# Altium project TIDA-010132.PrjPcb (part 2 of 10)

## Sheet AFE1.SchDoc
size 558 x 431 mm; Date: Not shown in title block; ApprovedBy: Not shown in title block; CheckedBy: Not shown in title block; Author: Not shown in title block; CompanyName: Not shown in title block; DrawnBy: Avinash N; Engineer: Not shown in title block; Organization: Not shown in title block; Address1: Not shown in title block; Address2: Not shown in title block; Address3: Not shown in title block; Address4: Not shown in title block; DocumentNumber: 1; Revision: Use project parameter SCH_Rev; SheetNumber: 4; SheetTotal: 32; PageSetup: Record=PageOptions¦CenterHorizontal=True¦CenterVertical=True¦PrintScale=1.00¦XCorrection=1.00¦YCorrection=1.00¦PrintKind=0¦BorderSize=5000000¦LeftOffset=0¦BottomOffset=0¦Orientation=2¦PaperLength=1000¦PaperWidth=1000¦Scale=100¦PaperSource=15¦PrintQuality=600¦MediaType=1¦DitherType=10¦PaperKind=Letter¦PrintScaleMode=1
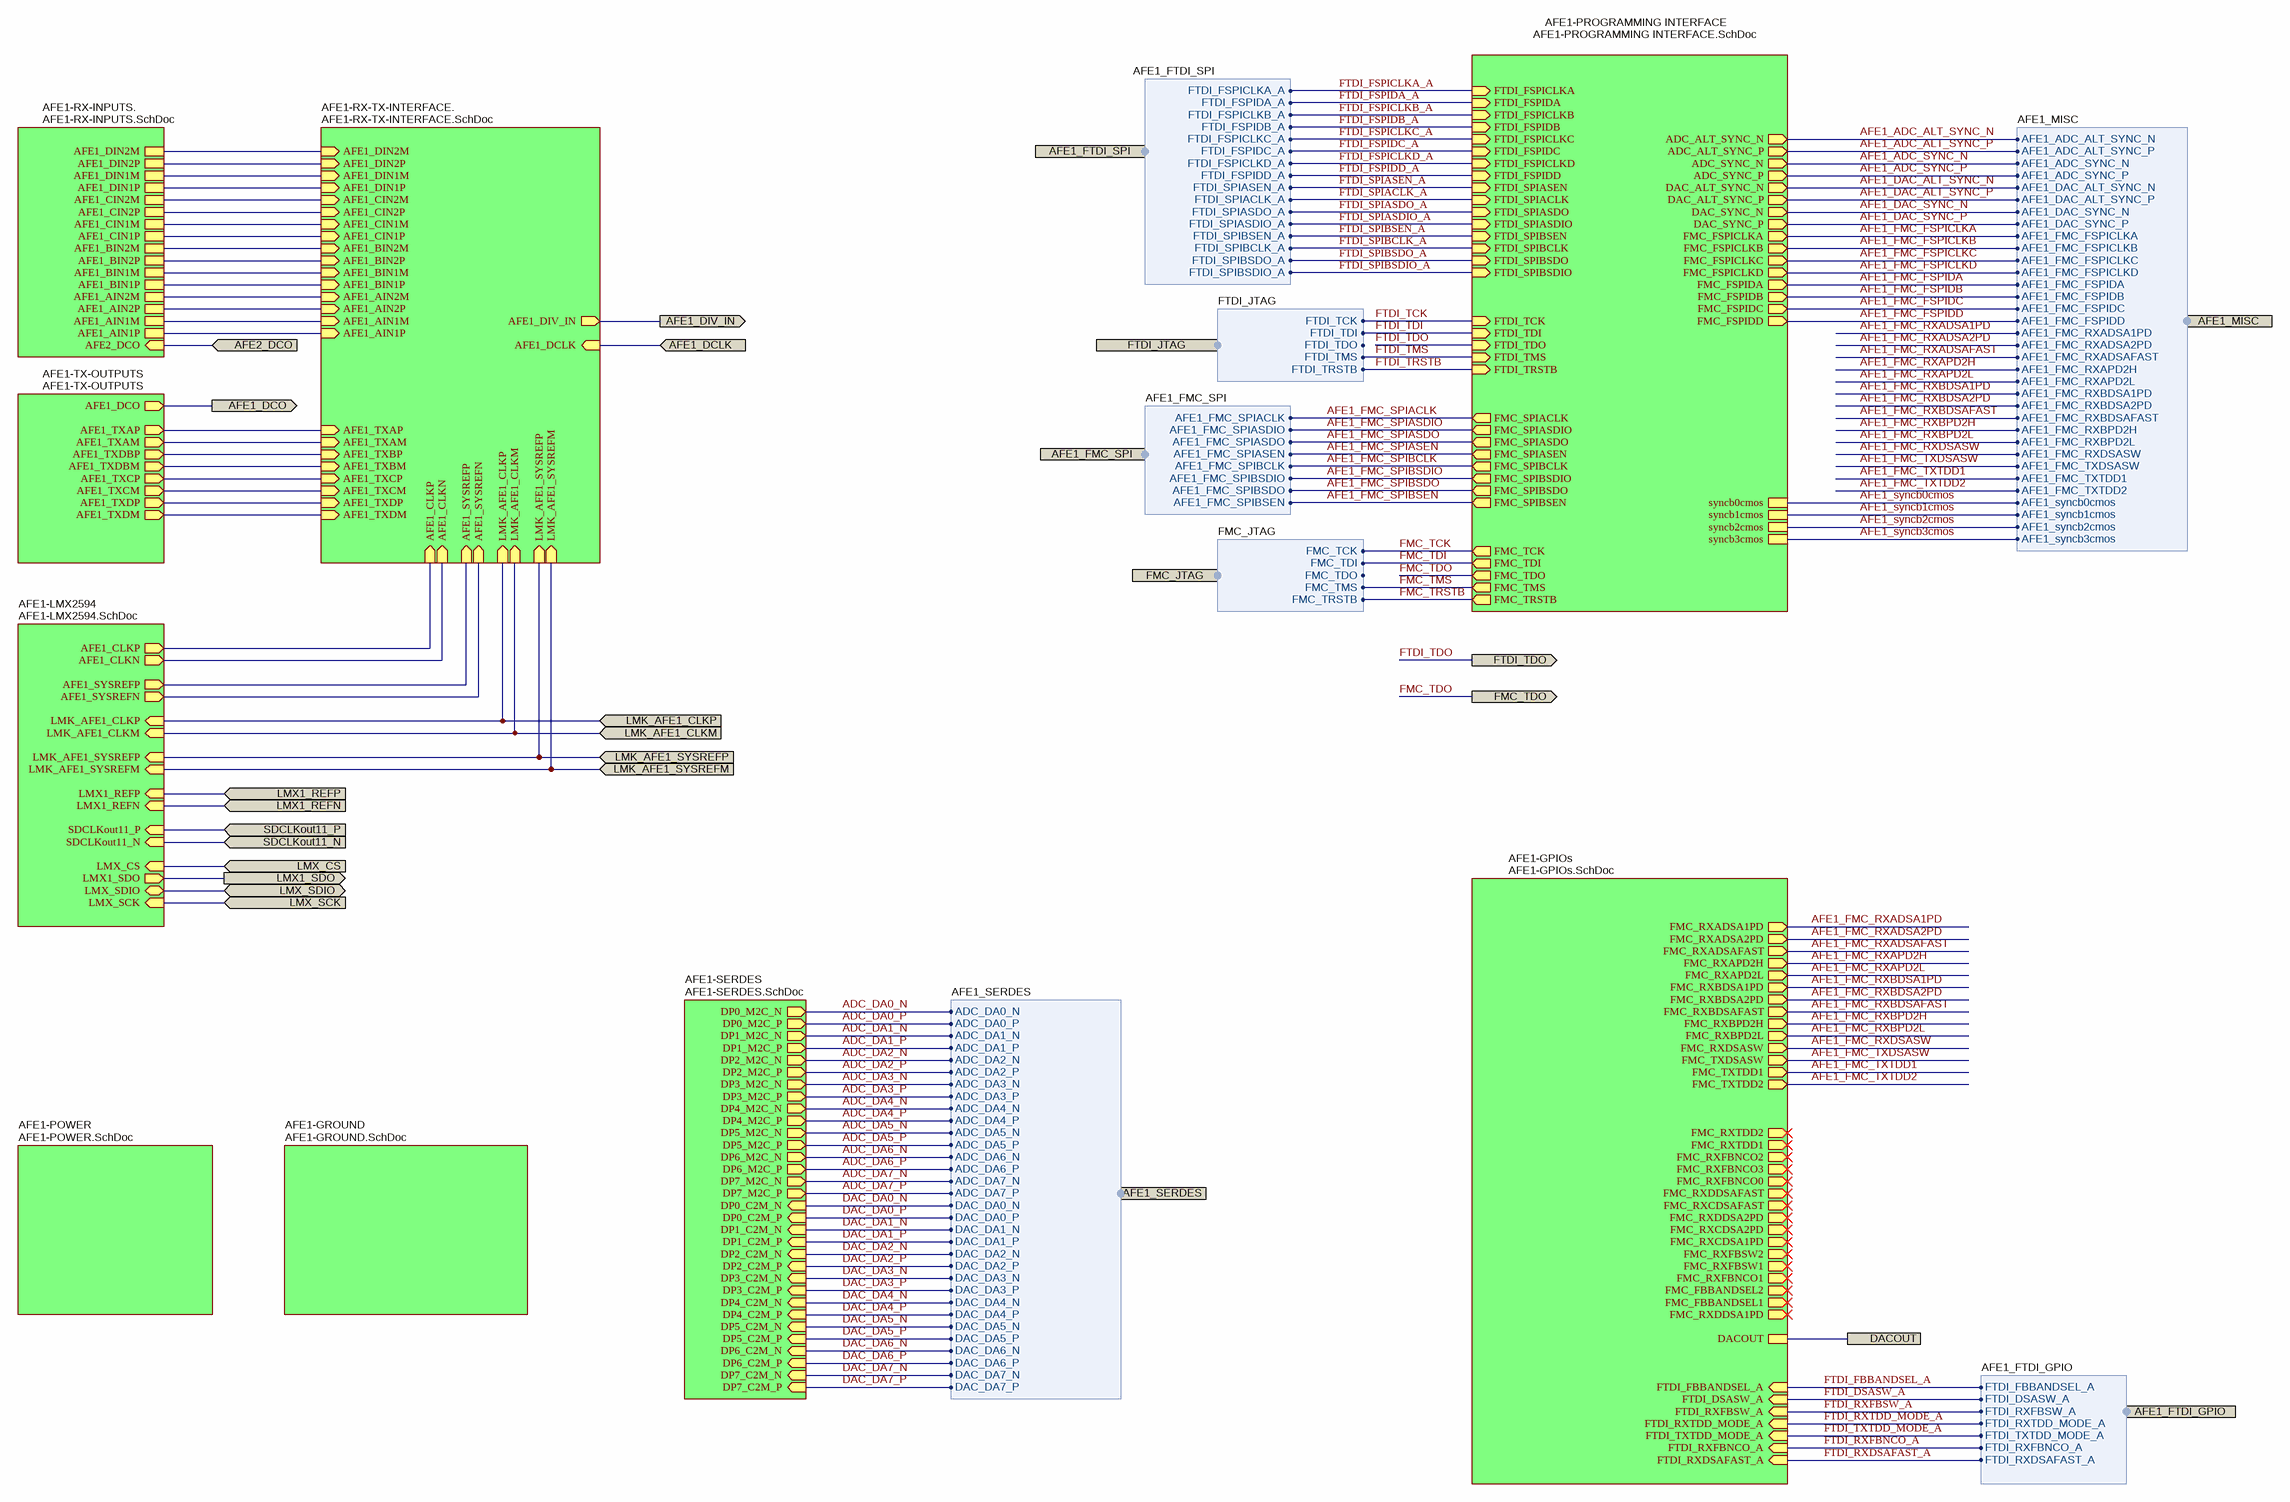
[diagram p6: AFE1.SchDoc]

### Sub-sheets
AFE1-GPIOs = AFE1-GPIOs.SchDoc: FMC_RXADSA1PD (out), FMC_RXADSA2PD (out), FMC_RXADSAFAST (out), FMC_RXAPD2H (out), FMC_RXAPD2L (out), FMC_RXBDSA1PD (out), FMC_RXBDSA2PD (out), FMC_RXBDSAFAST (out), FMC_RXBPD2H (out), FMC_RXBPD2L (out), FMC_RXDSASW (out), FMC_TXDSASW (out), FMC_TXTDD1 (out), FMC_TXTDD2 (out), FMC_RXTDD2 (out), FMC_RXTDD1 (out), FMC_RXFBNCO2 (out), FMC_RXFBNCO3 (out), FMC_RXFBNCO0 (out), FMC_RXDDSAFAST (out), FMC_RXCDSAFAST (out), FMC_RXDDSA2PD (out), FMC_RXCDSA2PD (out), FMC_RXCDSA1PD (out), FMC_RXFBSW2 (out), FMC_RXFBSW1 (out), FMC_RXFBNCO1 (out), FMC_FBBANDSEL2 (out), FMC_FBBANDSEL1 (out), DACOUT, FTDI_RXFBNCO_A (in), FTDI_RXDSAFAST_A (in), FTDI_DSASW_A (in), FTDI_RXFBSW_A (in), FTDI_RXTDD_MODE_A (in), FTDI_TXTDD_MODE_A (in), FTDI_FBBANDSEL_A (in), FMC_RXDDSA1PD (out)
AFE1-GROUND = AFE1-GROUND.SchDoc: no entries
AFE1-LMX2594 = AFE1-LMX2594.SchDoc: AFE1_CLKP (out), AFE1_CLKN (out), AFE1_SYSREFP (out), AFE1_SYSREFN (out), SDCLKout11_P (in), SDCLKout11_N (in), LMK_AFE1_CLKP (in), LMK_AFE1_CLKM (in), LMX_CS (in), LMX_SDIO (bidir), LMX_SCK (in), LMX1_SDO (out), LMK_AFE1_SYSREFP (in), LMK_AFE1_SYSREFM (in), LMX1_REFP (in), LMX1_REFN (in)
AFE1-POWER = AFE1-POWER.SchDoc: no entries
AFE1-PROGRAMMING INTERFACE = AFE1-PROGRAMMING INTERFACE.SchDoc: ADC_ALT_SYNC_P (out), ADC_ALT_SYNC_N (out), ADC_SYNC_P (out), ADC_SYNC_N (out), DAC_ALT_SYNC_P (out), DAC_ALT_SYNC_N (out), DAC_SYNC_P (out), DAC_SYNC_N (out), FMC_FSPICLKA (out), FMC_FSPICLKB (out), FMC_FSPICLKC (out), FMC_FSPICLKD (out), FMC_FSPIDA (out), FMC_FSPIDB (out), FMC_FSPIDC (out), FMC_FSPIDD (out), syncb0cmos, syncb1cmos, syncb2cmos, syncb3cmos, FMC_TMS (out), FMC_TCK (out), FMC_TDO (out), FMC_TDI (out), FMC_TRSTB (out), FMC_SPIASEN (out), FMC_SPIACLK (out), FMC_SPIASDO (out), FMC_SPIASDIO (out), FMC_SPIBSEN (out), FMC_SPIBCLK (out), FMC_SPIBSDO (out), FMC_SPIBSDIO (out), FTDI_TDI (in), FTDI_TDO (in), FTDI_TMS (in), FTDI_TRSTB (in), FTDI_TCK (in), FTDI_FSPIDD (in), FTDI_SPIASEN (in), FTDI_SPIBCLK (in), FTDI_SPIASDIO (in), FTDI_SPIBSEN (in), FTDI_SPIBSDO (in), FTDI_SPIBSDIO (in), FTDI_FSPIDC (in), FTDI_FSPICLKC (in), FTDI_FSPIDB (in), FTDI_FSPICLKB (in), FTDI_FSPIDA (in), FTDI_FSPICLKA (in), FTDI_FSPICLKD (in), FTDI_SPIASDO (in), FTDI_SPIACLK (in)
AFE1-RX-INPUTS. = AFE1-RX-INPUTS.SchDoc: AFE1_CIN1M, AFE1_BIN2P, AFE1_AIN2P, AFE1_DIN2P, AFE1_BIN2M, AFE1_CIN1P, AFE1_DIN2M, AFE1_AIN1M, AFE1_DIN1P, AFE1_BIN1M, AFE1_AIN2M, AFE1_DIN1M, AFE1_CIN2P, AFE1_CIN2M, AFE1_AIN1P, AFE1_BIN1P, AFE2_DCO (in)
AFE1-RX-TX-INTERFACE. = AFE1-RX-TX-INTERFACE.SchDoc: AFE1_DIN1M (in), AFE1_CIN1M (in), AFE1_BIN1M (in), AFE1_CIN2M (in), AFE1_AIN2M (in), AFE1_DIN2M (in), AFE1_DIN1P (in), AFE1_BIN2P (in), AFE1_CIN1P (in), AFE1_CLKN (in), AFE1_CLKP (in), AFE1_DIV_IN (out), AFE1_SYSREFN (in), AFE1_SYSREFP (in), AFE1_AIN1P (in), AFE1_AIN1M (in), AFE1_DIN2P (in), AFE1_CIN2P (in), AFE1_BIN2M (in), AFE1_BIN1P (in), AFE1_AIN2P (in), LMK_AFE1_CLKP (in), LMK_AFE1_CLKM (in), AFE1_TXAP (in), AFE1_TXAM (in), AFE1_TXBM (in), AFE1_TXBP (in), AFE1_TXCM (in), AFE1_TXCP (in), AFE1_TXDM (in), AFE1_TXDP (in), AFE1_DCLK (in), LMK_AFE1_SYSREFM (in), LMK_AFE1_SYSREFP (in)
AFE1-SERDES = AFE1-SERDES.SchDoc: DP1_M2C_N (out), DP1_M2C_P (out), DP5_C2M_P (in), DP3_M2C_P (out), DP7_M2C_P (out), DP3_M2C_N (out), DP7_M2C_N (out), DP6_M2C_P (out), DP7_C2M_P (in), DP2_M2C_P (out), DP6_C2M_P (in), DP2_M2C_N (out), DP0_M2C_P (out), DP0_M2C_N (out), DP4_C2M_N (in), DP2_C2M_N (in), DP0_C2M_P (in), DP5_M2C_P (out), DP6_C2M_N (in), DP6_M2C_N (out), DP4_C2M_P (in), DP3_C2M_N (in), DP4_M2C_P (out), DP1_C2M_N (in), DP3_C2M_P (in), DP5_M2C_N (out), DP0_C2M_N (in), DP4_M2C_N (out), DP2_C2M_P (in), DP7_C2M_N (in), DP1_C2M_P (in), DP5_C2M_N (in)
AFE1-TX-OUTPUTS = AFE1-TX-OUTPUTS: AFE1_TXAM (out), AFE1_TXAP (out), AFE1_TXDBM (out), AFE1_TXDBP (out), AFE1_TXCM (out), AFE1_TXCP (out), AFE1_TXDM (out), AFE1_TXDP (out), AFE1_DCO (out)

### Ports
AFE1_DCLK (in), AFE1_DCO (out), AFE1_DIV_IN (out), AFE1_FMC_SPI (harness AFE1_FMC_SPI), AFE1_FTDI_GPIO (harness AFE1_FTDI_GPIO), AFE1_FTDI_SPI (harness AFE1_FTDI_SPI), AFE1_MISC (harness AFE1_MISC), AFE1_SERDES (harness AFE1_SERDES), AFE2_DCO (in), DACOUT, FMC_JTAG (harness FMC_JTAG), FMC_TDO (out), FTDI_JTAG (harness FTDI_JTAG), FTDI_TDO (out), LMK_AFE1_CLKM (in), LMK_AFE1_CLKP (in), LMK_AFE1_SYSREFM (in), LMK_AFE1_SYSREFP (in), LMX1_REFN (in), LMX1_REFP (in), LMX1_SDO (out), LMX_CS (in), LMX_SCK (in), LMX_SDIO (bidir), SDCLKout11_N (in), SDCLKout11_P (in)

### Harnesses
AFE1_SERDES: ADC_DA0_N, ADC_DA0_P, ADC_DA1_N, ADC_DA1_P, ADC_DA2_N, ADC_DA2_P, ADC_DA3_N, ADC_DA3_P, ADC_DA4_N, ADC_DA4_P, ADC_DA5_N, ADC_DA5_P, ADC_DA6_N, ADC_DA6_P, ADC_DA7_N, ADC_DA7_P, DAC_DA0_N, DAC_DA0_P, DAC_DA1_N, DAC_DA1_P, DAC_DA2_N, DAC_DA2_P, DAC_DA3_N, DAC_DA3_P, DAC_DA4_N, DAC_DA4_P, DAC_DA5_N, DAC_DA5_P, DAC_DA6_N, DAC_DA6_P, DAC_DA7_N, DAC_DA7_P
AFE1_MISC: AFE1_ADC_ALT_SYNC_N, AFE1_ADC_ALT_SYNC_P, AFE1_ADC_SYNC_N, AFE1_ADC_SYNC_P, AFE1_DAC_ALT_SYNC_N, AFE1_DAC_ALT_SYNC_P, AFE1_DAC_SYNC_N, AFE1_DAC_SYNC_P, AFE1_FMC_FSPICLKA, AFE1_FMC_FSPICLKB, AFE1_FMC_FSPICLKC, AFE1_FMC_FSPICLKD, AFE1_FMC_FSPIDA, AFE1_FMC_FSPIDB, AFE1_FMC_FSPIDC, AFE1_FMC_FSPIDD, AFE1_FMC_RXADSA1PD, AFE1_FMC_RXADSA2PD, AFE1_FMC_RXADSAFAST, AFE1_FMC_RXAPD2H, AFE1_FMC_RXAPD2L, AFE1_FMC_RXBDSA1PD, AFE1_FMC_RXBDSA2PD, AFE1_FMC_RXBDSAFAST, AFE1_FMC_RXBPD2H, AFE1_FMC_RXBPD2L, AFE1_FMC_RXDSASW, AFE1_FMC_TXDSASW, AFE1_FMC_TXTDD1, AFE1_FMC_TXTDD2, AFE1_syncb0cmos, AFE1_syncb1cmos, AFE1_syncb2cmos, AFE1_syncb3cmos
FMC_JTAG: FMC_TCK, FMC_TDI, FMC_TDO, FMC_TMS, FMC_TRSTB
AFE1_FTDI_GPIO: FTDI_FBBANDSEL_A, FTDI_DSASW_A, FTDI_RXFBSW_A, FTDI_RXTDD_MODE_A, FTDI_TXTDD_MODE_A, FTDI_RXFBNCO_A, FTDI_RXDSAFAST_A
FTDI_JTAG: FTDI_TCK, FTDI_TDI, FTDI_TDO, FTDI_TMS, FTDI_TRSTB
AFE1_FTDI_SPI: FTDI_FSPICLKA_A, FTDI_FSPIDA_A, FTDI_FSPICLKB_A, FTDI_FSPIDB_A, FTDI_FSPICLKC_A, FTDI_FSPIDC_A, FTDI_FSPICLKD_A, FTDI_FSPIDD_A, FTDI_SPIASEN_A, FTDI_SPIACLK_A, FTDI_SPIASDO_A, FTDI_SPIASDIO_A, FTDI_SPIBSEN_A, FTDI_SPIBCLK_A, FTDI_SPIBSDO_A, FTDI_SPIBSDIO_A
AFE1_FMC_SPI: AFE1_FMC_SPIACLK, AFE1_FMC_SPIASDIO, AFE1_FMC_SPIASDO, AFE1_FMC_SPIASEN, AFE1_FMC_SPIBCLK, AFE1_FMC_SPIBSDIO, AFE1_FMC_SPIBSDO, AFE1_FMC_SPIBSEN

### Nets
ADC_DA0_N: sheet AFE1-SERDES/DP0_M2C_N, port AFE1_SERDES.ADC_DA0_N
ADC_DA0_P: sheet AFE1-SERDES/DP0_M2C_P, port AFE1_SERDES.ADC_DA0_P
ADC_DA1_N: sheet AFE1-SERDES/DP1_M2C_N, port AFE1_SERDES.ADC_DA1_N
ADC_DA1_P: sheet AFE1-SERDES/DP1_M2C_P, port AFE1_SERDES.ADC_DA1_P
ADC_DA2_N: sheet AFE1-SERDES/DP2_M2C_N, port AFE1_SERDES.ADC_DA2_N
ADC_DA2_P: sheet AFE1-SERDES/DP2_M2C_P, port AFE1_SERDES.ADC_DA2_P
ADC_DA3_N: sheet AFE1-SERDES/DP3_M2C_N, port AFE1_SERDES.ADC_DA3_N
ADC_DA3_P: sheet AFE1-SERDES/DP3_M2C_P, port AFE1_SERDES.ADC_DA3_P
ADC_DA4_N: sheet AFE1-SERDES/DP4_M2C_N, port AFE1_SERDES.ADC_DA4_N
ADC_DA4_P: sheet AFE1-SERDES/DP4_M2C_P, port AFE1_SERDES.ADC_DA4_P
ADC_DA5_N: sheet AFE1-SERDES/DP5_M2C_N, port AFE1_SERDES.ADC_DA5_N
ADC_DA5_P: sheet AFE1-SERDES/DP5_M2C_P, port AFE1_SERDES.ADC_DA5_P
ADC_DA6_N: sheet AFE1-SERDES/DP6_M2C_N, port AFE1_SERDES.ADC_DA6_N
ADC_DA6_P: sheet AFE1-SERDES/DP6_M2C_P, port AFE1_SERDES.ADC_DA6_P
ADC_DA7_N: sheet AFE1-SERDES/DP7_M2C_N, port AFE1_SERDES.ADC_DA7_N
ADC_DA7_P: sheet AFE1-SERDES/DP7_M2C_P, port AFE1_SERDES.ADC_DA7_P
AFE1_ADC_ALT_SYNC_N: sheet AFE1-PROGRAMMING INTERFACE/ADC_ALT_SYNC_N, port AFE1_MISC.AFE1_ADC_ALT_SYNC_N
AFE1_ADC_ALT_SYNC_P: sheet AFE1-PROGRAMMING INTERFACE/ADC_ALT_SYNC_P, port AFE1_MISC.AFE1_ADC_ALT_SYNC_P
AFE1_ADC_SYNC_N: sheet AFE1-PROGRAMMING INTERFACE/ADC_SYNC_N, port AFE1_MISC.AFE1_ADC_SYNC_N
AFE1_ADC_SYNC_P: sheet AFE1-PROGRAMMING INTERFACE/ADC_SYNC_P, port AFE1_MISC.AFE1_ADC_SYNC_P
AFE1_DAC_ALT_SYNC_N: sheet AFE1-PROGRAMMING INTERFACE/DAC_ALT_SYNC_N, port AFE1_MISC.AFE1_DAC_ALT_SYNC_N
AFE1_DAC_ALT_SYNC_P: sheet AFE1-PROGRAMMING INTERFACE/DAC_ALT_SYNC_P, port AFE1_MISC.AFE1_DAC_ALT_SYNC_P
AFE1_DAC_SYNC_N: sheet AFE1-PROGRAMMING INTERFACE/DAC_SYNC_N, port AFE1_MISC.AFE1_DAC_SYNC_N
AFE1_DAC_SYNC_P: sheet AFE1-PROGRAMMING INTERFACE/DAC_SYNC_P, port AFE1_MISC.AFE1_DAC_SYNC_P
AFE1_DCLK: port AFE1_DCLK, sheet AFE1-RX-TX-INTERFACE./AFE1_DCLK
AFE1_DCO: port AFE1_DCO, sheet AFE1-TX-OUTPUTS/AFE1_DCO
AFE1_DIV_IN: port AFE1_DIV_IN, sheet AFE1-RX-TX-INTERFACE./AFE1_DIV_IN
AFE1_FMC_FSPICLKA: sheet AFE1-PROGRAMMING INTERFACE/FMC_FSPICLKA, port AFE1_MISC.AFE1_FMC_FSPICLKA
AFE1_FMC_FSPICLKB: sheet AFE1-PROGRAMMING INTERFACE/FMC_FSPICLKB, port AFE1_MISC.AFE1_FMC_FSPICLKB
AFE1_FMC_FSPICLKC: sheet AFE1-PROGRAMMING INTERFACE/FMC_FSPICLKC, port AFE1_MISC.AFE1_FMC_FSPICLKC
AFE1_FMC_FSPICLKD: sheet AFE1-PROGRAMMING INTERFACE/FMC_FSPICLKD, port AFE1_MISC.AFE1_FMC_FSPICLKD
AFE1_FMC_FSPIDA: sheet AFE1-PROGRAMMING INTERFACE/FMC_FSPIDA, port AFE1_MISC.AFE1_FMC_FSPIDA
AFE1_FMC_FSPIDB: sheet AFE1-PROGRAMMING INTERFACE/FMC_FSPIDB, port AFE1_MISC.AFE1_FMC_FSPIDB
AFE1_FMC_FSPIDC: sheet AFE1-PROGRAMMING INTERFACE/FMC_FSPIDC, port AFE1_MISC.AFE1_FMC_FSPIDC
AFE1_FMC_FSPIDD: sheet AFE1-PROGRAMMING INTERFACE/FMC_FSPIDD, port AFE1_MISC.AFE1_FMC_FSPIDD
AFE1_FMC_RXADSA1PD: sheet AFE1-GPIOs/FMC_RXADSA1PD, port AFE1_MISC.AFE1_FMC_RXADSA1PD
AFE1_FMC_RXADSA2PD: sheet AFE1-GPIOs/FMC_RXADSA2PD, port AFE1_MISC.AFE1_FMC_RXADSA2PD
AFE1_FMC_RXADSAFAST: sheet AFE1-GPIOs/FMC_RXADSAFAST, port AFE1_MISC.AFE1_FMC_RXADSAFAST
AFE1_FMC_RXAPD2H: sheet AFE1-GPIOs/FMC_RXAPD2H, port AFE1_MISC.AFE1_FMC_RXAPD2H
AFE1_FMC_RXAPD2L: sheet AFE1-GPIOs/FMC_RXAPD2L, port AFE1_MISC.AFE1_FMC_RXAPD2L
AFE1_FMC_RXBDSA1PD: sheet AFE1-GPIOs/FMC_RXBDSA1PD, port AFE1_MISC.AFE1_FMC_RXBDSA1PD
AFE1_FMC_RXBDSA2PD: sheet AFE1-GPIOs/FMC_RXBDSA2PD, port AFE1_MISC.AFE1_FMC_RXBDSA2PD
AFE1_FMC_RXBDSAFAST: sheet AFE1-GPIOs/FMC_RXBDSAFAST, port AFE1_MISC.AFE1_FMC_RXBDSAFAST
AFE1_FMC_RXBPD2H: sheet AFE1-GPIOs/FMC_RXBPD2H, port AFE1_MISC.AFE1_FMC_RXBPD2H
AFE1_FMC_RXBPD2L: sheet AFE1-GPIOs/FMC_RXBPD2L, port AFE1_MISC.AFE1_FMC_RXBPD2L
AFE1_FMC_RXDSASW: sheet AFE1-GPIOs/FMC_RXDSASW, port AFE1_MISC.AFE1_FMC_RXDSASW
AFE1_FMC_SPIACLK: sheet AFE1-PROGRAMMING INTERFACE/FMC_SPIACLK, port AFE1_FMC_SPI.AFE1_FMC_SPIACLK
AFE1_FMC_SPIASDIO: sheet AFE1-PROGRAMMING INTERFACE/FMC_SPIASDIO, port AFE1_FMC_SPI.AFE1_FMC_SPIASDIO
AFE1_FMC_SPIASDO: sheet AFE1-PROGRAMMING INTERFACE/FMC_SPIASDO, port AFE1_FMC_SPI.AFE1_FMC_SPIASDO
AFE1_FMC_SPIASEN: sheet AFE1-PROGRAMMING INTERFACE/FMC_SPIASEN, port AFE1_FMC_SPI.AFE1_FMC_SPIASEN
AFE1_FMC_SPIBCLK: sheet AFE1-PROGRAMMING INTERFACE/FMC_SPIBCLK, port AFE1_FMC_SPI.AFE1_FMC_SPIBCLK
AFE1_FMC_SPIBSDIO: sheet AFE1-PROGRAMMING INTERFACE/FMC_SPIBSDIO, port AFE1_FMC_SPI.AFE1_FMC_SPIBSDIO
AFE1_FMC_SPIBSDO: sheet AFE1-PROGRAMMING INTERFACE/FMC_SPIBSDO, port AFE1_FMC_SPI.AFE1_FMC_SPIBSDO
AFE1_FMC_SPIBSEN: sheet AFE1-PROGRAMMING INTERFACE/FMC_SPIBSEN, port AFE1_FMC_SPI.AFE1_FMC_SPIBSEN
AFE1_FMC_TXDSASW: sheet AFE1-GPIOs/FMC_TXDSASW, port AFE1_MISC.AFE1_FMC_TXDSASW
AFE1_FMC_TXTDD1: sheet AFE1-GPIOs/FMC_TXTDD1, port AFE1_MISC.AFE1_FMC_TXTDD1
AFE1_FMC_TXTDD2: sheet AFE1-GPIOs/FMC_TXTDD2, port AFE1_MISC.AFE1_FMC_TXTDD2
AFE1_syncb0cmos: sheet AFE1-PROGRAMMING INTERFACE/syncb0cmos, port AFE1_MISC.AFE1_syncb0cmos
AFE1_syncb1cmos: sheet AFE1-PROGRAMMING INTERFACE/syncb1cmos, port AFE1_MISC.AFE1_syncb1cmos
AFE1_syncb2cmos: sheet AFE1-PROGRAMMING INTERFACE/syncb2cmos, port AFE1_MISC.AFE1_syncb2cmos
AFE1_syncb3cmos: sheet AFE1-PROGRAMMING INTERFACE/syncb3cmos, port AFE1_MISC.AFE1_syncb3cmos
AFE2_DCO: port AFE2_DCO, sheet AFE1-RX-INPUTS./AFE2_DCO
DAC_DA0_N: sheet AFE1-SERDES/DP0_C2M_N, port AFE1_SERDES.DAC_DA0_N
DAC_DA0_P: sheet AFE1-SERDES/DP0_C2M_P, port AFE1_SERDES.DAC_DA0_P
DAC_DA1_N: sheet AFE1-SERDES/DP1_C2M_N, port AFE1_SERDES.DAC_DA1_N
DAC_DA1_P: sheet AFE1-SERDES/DP1_C2M_P, port AFE1_SERDES.DAC_DA1_P
DAC_DA2_N: sheet AFE1-SERDES/DP2_C2M_N, port AFE1_SERDES.DAC_DA2_N
DAC_DA2_P: sheet AFE1-SERDES/DP2_C2M_P, port AFE1_SERDES.DAC_DA2_P
DAC_DA3_N: sheet AFE1-SERDES/DP3_C2M_N, port AFE1_SERDES.DAC_DA3_N
DAC_DA3_P: sheet AFE1-SERDES/DP3_C2M_P, port AFE1_SERDES.DAC_DA3_P
DAC_DA4_N: sheet AFE1-SERDES/DP4_C2M_N, port AFE1_SERDES.DAC_DA4_N
DAC_DA4_P: sheet AFE1-SERDES/DP4_C2M_P, port AFE1_SERDES.DAC_DA4_P
DAC_DA5_N: sheet AFE1-SERDES/DP5_C2M_N, port AFE1_SERDES.DAC_DA5_N
DAC_DA5_P: sheet AFE1-SERDES/DP5_C2M_P, port AFE1_SERDES.DAC_DA5_P
DAC_DA6_N: sheet AFE1-SERDES/DP6_C2M_N, port AFE1_SERDES.DAC_DA6_N
DAC_DA6_P: sheet AFE1-SERDES/DP6_C2M_P, port AFE1_SERDES.DAC_DA6_P
DAC_DA7_N: sheet AFE1-SERDES/DP7_C2M_N, port AFE1_SERDES.DAC_DA7_N
DAC_DA7_P: sheet AFE1-SERDES/DP7_C2M_P, port AFE1_SERDES.DAC_DA7_P
DACOUT: port DACOUT, sheet AFE1-GPIOs/DACOUT
FMC_TCK: sheet AFE1-PROGRAMMING INTERFACE/FMC_TCK, port FMC_JTAG.FMC_TCK
FMC_TDI: sheet AFE1-PROGRAMMING INTERFACE/FMC_TDI, port FMC_JTAG.FMC_TDI
FMC_TDO: port FMC_TDO, sheet AFE1-PROGRAMMING INTERFACE/FMC_TDO
FMC_TMS: sheet AFE1-PROGRAMMING INTERFACE/FMC_TMS, port FMC_JTAG.FMC_TMS
FMC_TRSTB: sheet AFE1-PROGRAMMING INTERFACE/FMC_TRSTB, port FMC_JTAG.FMC_TRSTB
FTDI_DSASW_A: sheet AFE1-GPIOs/FTDI_DSASW_A, port AFE1_FTDI_GPIO.FTDI_DSASW_A
FTDI_FBBANDSEL_A: sheet AFE1-GPIOs/FTDI_FBBANDSEL_A, port AFE1_FTDI_GPIO.FTDI_FBBANDSEL_A
FTDI_FSPICLKA_A: sheet AFE1-PROGRAMMING INTERFACE/FTDI_FSPICLKA, port AFE1_FTDI_SPI.FTDI_FSPICLKA_A
FTDI_FSPICLKB_A: sheet AFE1-PROGRAMMING INTERFACE/FTDI_FSPICLKB, port AFE1_FTDI_SPI.FTDI_FSPICLKB_A
FTDI_FSPICLKC_A: sheet AFE1-PROGRAMMING INTERFACE/FTDI_FSPICLKC, port AFE1_FTDI_SPI.FTDI_FSPICLKC_A
FTDI_FSPICLKD_A: sheet AFE1-PROGRAMMING INTERFACE/FTDI_FSPICLKD, port AFE1_FTDI_SPI.FTDI_FSPICLKD_A
FTDI_FSPIDA_A: sheet AFE1-PROGRAMMING INTERFACE/FTDI_FSPIDA, port AFE1_FTDI_SPI.FTDI_FSPIDA_A
FTDI_FSPIDB_A: sheet AFE1-PROGRAMMING INTERFACE/FTDI_FSPIDB, port AFE1_FTDI_SPI.FTDI_FSPIDB_A
FTDI_FSPIDC_A: sheet AFE1-PROGRAMMING INTERFACE/FTDI_FSPIDC, port AFE1_FTDI_SPI.FTDI_FSPIDC_A
FTDI_FSPIDD_A: sheet AFE1-PROGRAMMING INTERFACE/FTDI_FSPIDD, port AFE1_FTDI_SPI.FTDI_FSPIDD_A
FTDI_RXDSAFAST_A: sheet AFE1-GPIOs/FTDI_RXDSAFAST_A, port AFE1_FTDI_GPIO.FTDI_RXDSAFAST_A
FTDI_RXFBNCO_A: sheet AFE1-GPIOs/FTDI_RXFBNCO_A, port AFE1_FTDI_GPIO.FTDI_RXFBNCO_A
FTDI_RXFBSW_A: sheet AFE1-GPIOs/FTDI_RXFBSW_A, port AFE1_FTDI_GPIO.FTDI_RXFBSW_A
FTDI_RXTDD_MODE_A: sheet AFE1-GPIOs/FTDI_RXTDD_MODE_A, port AFE1_FTDI_GPIO.FTDI_RXTDD_MODE_A
FTDI_SPIACLK_A: sheet AFE1-PROGRAMMING INTERFACE/FTDI_SPIACLK, port AFE1_FTDI_SPI.FTDI_SPIACLK_A
FTDI_SPIASDIO_A: sheet AFE1-PROGRAMMING INTERFACE/FTDI_SPIASDIO, port AFE1_FTDI_SPI.FTDI_SPIASDIO_A
FTDI_SPIASDO_A: sheet AFE1-PROGRAMMING INTERFACE/FTDI_SPIASDO, port AFE1_FTDI_SPI.FTDI_SPIASDO_A
FTDI_SPIASEN_A: sheet AFE1-PROGRAMMING INTERFACE/FTDI_SPIASEN, port AFE1_FTDI_SPI.FTDI_SPIASEN_A
FTDI_SPIBCLK_A: sheet AFE1-PROGRAMMING INTERFACE/FTDI_SPIBCLK, port AFE1_FTDI_SPI.FTDI_SPIBCLK_A
FTDI_SPIBSDIO_A: sheet AFE1-PROGRAMMING INTERFACE/FTDI_SPIBSDIO, port AFE1_FTDI_SPI.FTDI_SPIBSDIO_A
FTDI_SPIBSDO_A: sheet AFE1-PROGRAMMING INTERFACE/FTDI_SPIBSDO, port AFE1_FTDI_SPI.FTDI_SPIBSDO_A
FTDI_SPIBSEN_A: sheet AFE1-PROGRAMMING INTERFACE/FTDI_SPIBSEN, port AFE1_FTDI_SPI.FTDI_SPIBSEN_A
FTDI_TCK: sheet AFE1-PROGRAMMING INTERFACE/FTDI_TCK, port FTDI_JTAG.FTDI_TCK
FTDI_TDI: sheet AFE1-PROGRAMMING INTERFACE/FTDI_TDI, port FTDI_JTAG.FTDI_TDI
FTDI_TDO: port FTDI_TDO, sheet AFE1-PROGRAMMING INTERFACE/FTDI_TDO
FTDI_TMS: sheet AFE1-PROGRAMMING INTERFACE/FTDI_TMS, port FTDI_JTAG.FTDI_TMS
FTDI_TRSTB: sheet AFE1-PROGRAMMING INTERFACE/FTDI_TRSTB, port FTDI_JTAG.FTDI_TRSTB
FTDI_TXTDD_MODE_A: sheet AFE1-GPIOs/FTDI_TXTDD_MODE_A, port AFE1_FTDI_GPIO.FTDI_TXTDD_MODE_A
LMK_AFE1_CLKM: port LMK_AFE1_CLKM, sheet AFE1-LMX2594/LMK_AFE1_CLKM, sheet AFE1-RX-TX-INTERFACE./LMK_AFE1_CLKM
LMK_AFE1_CLKP: port LMK_AFE1_CLKP, sheet AFE1-LMX2594/LMK_AFE1_CLKP, sheet AFE1-RX-TX-INTERFACE./LMK_AFE1_CLKP
LMK_AFE1_SYSREFM: port LMK_AFE1_SYSREFM, sheet AFE1-LMX2594/LMK_AFE1_SYSREFM, sheet AFE1-RX-TX-INTERFACE./LMK_AFE1_SYSREFM
LMK_AFE1_SYSREFP: port LMK_AFE1_SYSREFP, sheet AFE1-LMX2594/LMK_AFE1_SYSREFP, sheet AFE1-RX-TX-INTERFACE./LMK_AFE1_SYSREFP
LMX1_REFN: port LMX1_REFN, sheet AFE1-LMX2594/LMX1_REFN
LMX1_REFP: port LMX1_REFP, sheet AFE1-LMX2594/LMX1_REFP
LMX1_SDO: port LMX1_SDO, sheet AFE1-LMX2594/LMX1_SDO
LMX_CS: port LMX_CS, sheet AFE1-LMX2594/LMX_CS
LMX_SCK: port LMX_SCK, sheet AFE1-LMX2594/LMX_SCK
LMX_SDIO: port LMX_SDIO, sheet AFE1-LMX2594/LMX_SDIO
SDCLKout11_N: port SDCLKout11_N, sheet AFE1-LMX2594/SDCLKout11_N
SDCLKout11_P: port SDCLKout11_P, sheet AFE1-LMX2594/SDCLKout11_P
(unnamed): sheet AFE1-RX-INPUTS./AFE1_CIN1M, sheet AFE1-RX-TX-INTERFACE./AFE1_CIN1M
(unnamed): sheet AFE1-RX-INPUTS./AFE1_BIN2P, sheet AFE1-RX-TX-INTERFACE./AFE1_BIN2P  [a separate net that carries the same name]
(unnamed): sheet AFE1-RX-INPUTS./AFE1_AIN2P, sheet AFE1-RX-TX-INTERFACE./AFE1_AIN2P  [a separate net that carries the same name]
(unnamed): sheet AFE1-RX-INPUTS./AFE1_DIN2P, sheet AFE1-RX-TX-INTERFACE./AFE1_DIN2P  [a separate net that carries the same name]
(unnamed): sheet AFE1-RX-INPUTS./AFE1_BIN2M, sheet AFE1-RX-TX-INTERFACE./AFE1_BIN2M  [a separate net that carries the same name]
(unnamed): sheet AFE1-RX-INPUTS./AFE1_CIN1P, sheet AFE1-RX-TX-INTERFACE./AFE1_CIN1P  [a separate net that carries the same name]
(unnamed): sheet AFE1-RX-INPUTS./AFE1_DIN2M, sheet AFE1-RX-TX-INTERFACE./AFE1_DIN2M  [a separate net that carries the same name]
(unnamed): sheet AFE1-RX-INPUTS./AFE1_AIN1M, sheet AFE1-RX-TX-INTERFACE./AFE1_AIN1M  [a separate net that carries the same name]
(unnamed): sheet AFE1-RX-INPUTS./AFE1_DIN1P, sheet AFE1-RX-TX-INTERFACE./AFE1_DIN1P  [a separate net that carries the same name]
(unnamed): sheet AFE1-RX-INPUTS./AFE1_BIN1M, sheet AFE1-RX-TX-INTERFACE./AFE1_BIN1M  [a separate net that carries the same name]
(unnamed): sheet AFE1-RX-INPUTS./AFE1_AIN2M, sheet AFE1-RX-TX-INTERFACE./AFE1_AIN2M  [a separate net that carries the same name]
(unnamed): sheet AFE1-RX-INPUTS./AFE1_DIN1M, sheet AFE1-RX-TX-INTERFACE./AFE1_DIN1M  [a separate net that carries the same name]
(unnamed): sheet AFE1-RX-INPUTS./AFE1_CIN2P, sheet AFE1-RX-TX-INTERFACE./AFE1_CIN2P  [a separate net that carries the same name]
(unnamed): sheet AFE1-RX-INPUTS./AFE1_CIN2M, sheet AFE1-RX-TX-INTERFACE./AFE1_CIN2M  [a separate net that carries the same name]
(unnamed): sheet AFE1-RX-INPUTS./AFE1_AIN1P, sheet AFE1-RX-TX-INTERFACE./AFE1_AIN1P  [a separate net that carries the same name]
(unnamed): sheet AFE1-RX-INPUTS./AFE1_BIN1P, sheet AFE1-RX-TX-INTERFACE./AFE1_BIN1P  [a separate net that carries the same name]
(unnamed): sheet AFE1-TX-OUTPUTS/AFE1_TXAM, sheet AFE1-RX-TX-INTERFACE./AFE1_TXAM  [a separate net that carries the same name]
(unnamed): sheet AFE1-TX-OUTPUTS/AFE1_TXAP, sheet AFE1-RX-TX-INTERFACE./AFE1_TXAP  [a separate net that carries the same name]
(unnamed): sheet AFE1-TX-OUTPUTS/AFE1_TXDBM, sheet AFE1-RX-TX-INTERFACE./AFE1_TXBM  [a separate net that carries the same name]
(unnamed): sheet AFE1-TX-OUTPUTS/AFE1_TXDBP, sheet AFE1-RX-TX-INTERFACE./AFE1_TXBP  [a separate net that carries the same name]
(unnamed): sheet AFE1-TX-OUTPUTS/AFE1_TXCM, sheet AFE1-RX-TX-INTERFACE./AFE1_TXCM  [a separate net that carries the same name]
(unnamed): sheet AFE1-TX-OUTPUTS/AFE1_TXCP, sheet AFE1-RX-TX-INTERFACE./AFE1_TXCP  [a separate net that carries the same name]
(unnamed): sheet AFE1-TX-OUTPUTS/AFE1_TXDM, sheet AFE1-RX-TX-INTERFACE./AFE1_TXDM  [a separate net that carries the same name]
(unnamed): sheet AFE1-TX-OUTPUTS/AFE1_TXDP, sheet AFE1-RX-TX-INTERFACE./AFE1_TXDP  [a separate net that carries the same name]
(unnamed): sheet AFE1-LMX2594/AFE1_CLKP, sheet AFE1-RX-TX-INTERFACE./AFE1_CLKP  [a separate net that carries the same name]
(unnamed): sheet AFE1-LMX2594/AFE1_CLKN, sheet AFE1-RX-TX-INTERFACE./AFE1_CLKN  [a separate net that carries the same name]
(unnamed): sheet AFE1-LMX2594/AFE1_SYSREFP, sheet AFE1-RX-TX-INTERFACE./AFE1_SYSREFP  [a separate net that carries the same name]
(unnamed): sheet AFE1-LMX2594/AFE1_SYSREFN, sheet AFE1-RX-TX-INTERFACE./AFE1_SYSREFN  [a separate net that carries the same name]

## Sheet AFE1-RX-INPUTS.SchDoc
size 431 x 279 mm; Date: Not shown in title block; ApprovedBy: Not shown in title block; CheckedBy: Not shown in title block; Author: Not shown in title block; CompanyName: Not shown in title block; DrawnBy: Avinash N; Engineer: Not shown in title block; Organization: Not shown in title block; Address1: Not shown in title block; Address2: Not shown in title block; Address3: Not shown in title block; Address4: Not shown in title block; DocumentNumber: 1; Revision: Use project parameter SCH_Rev; SheetNumber: 6; SheetTotal: 32; PageSetup: Record=PageOptions¦CenterHorizontal=True¦CenterVertical=True¦PrintScale=1.00¦XCorrection=1.00¦YCorrection=1.00¦PrintKind=0¦BorderSize=5000000¦LeftOffset=0¦BottomOffset=0¦Orientation=2¦PaperLength=1000¦PaperWidth=1000¦Scale=100¦PaperSource=15¦PrintQuality=600¦MediaType=1¦DitherType=10¦PaperKind=Letter¦PrintScaleMode=1
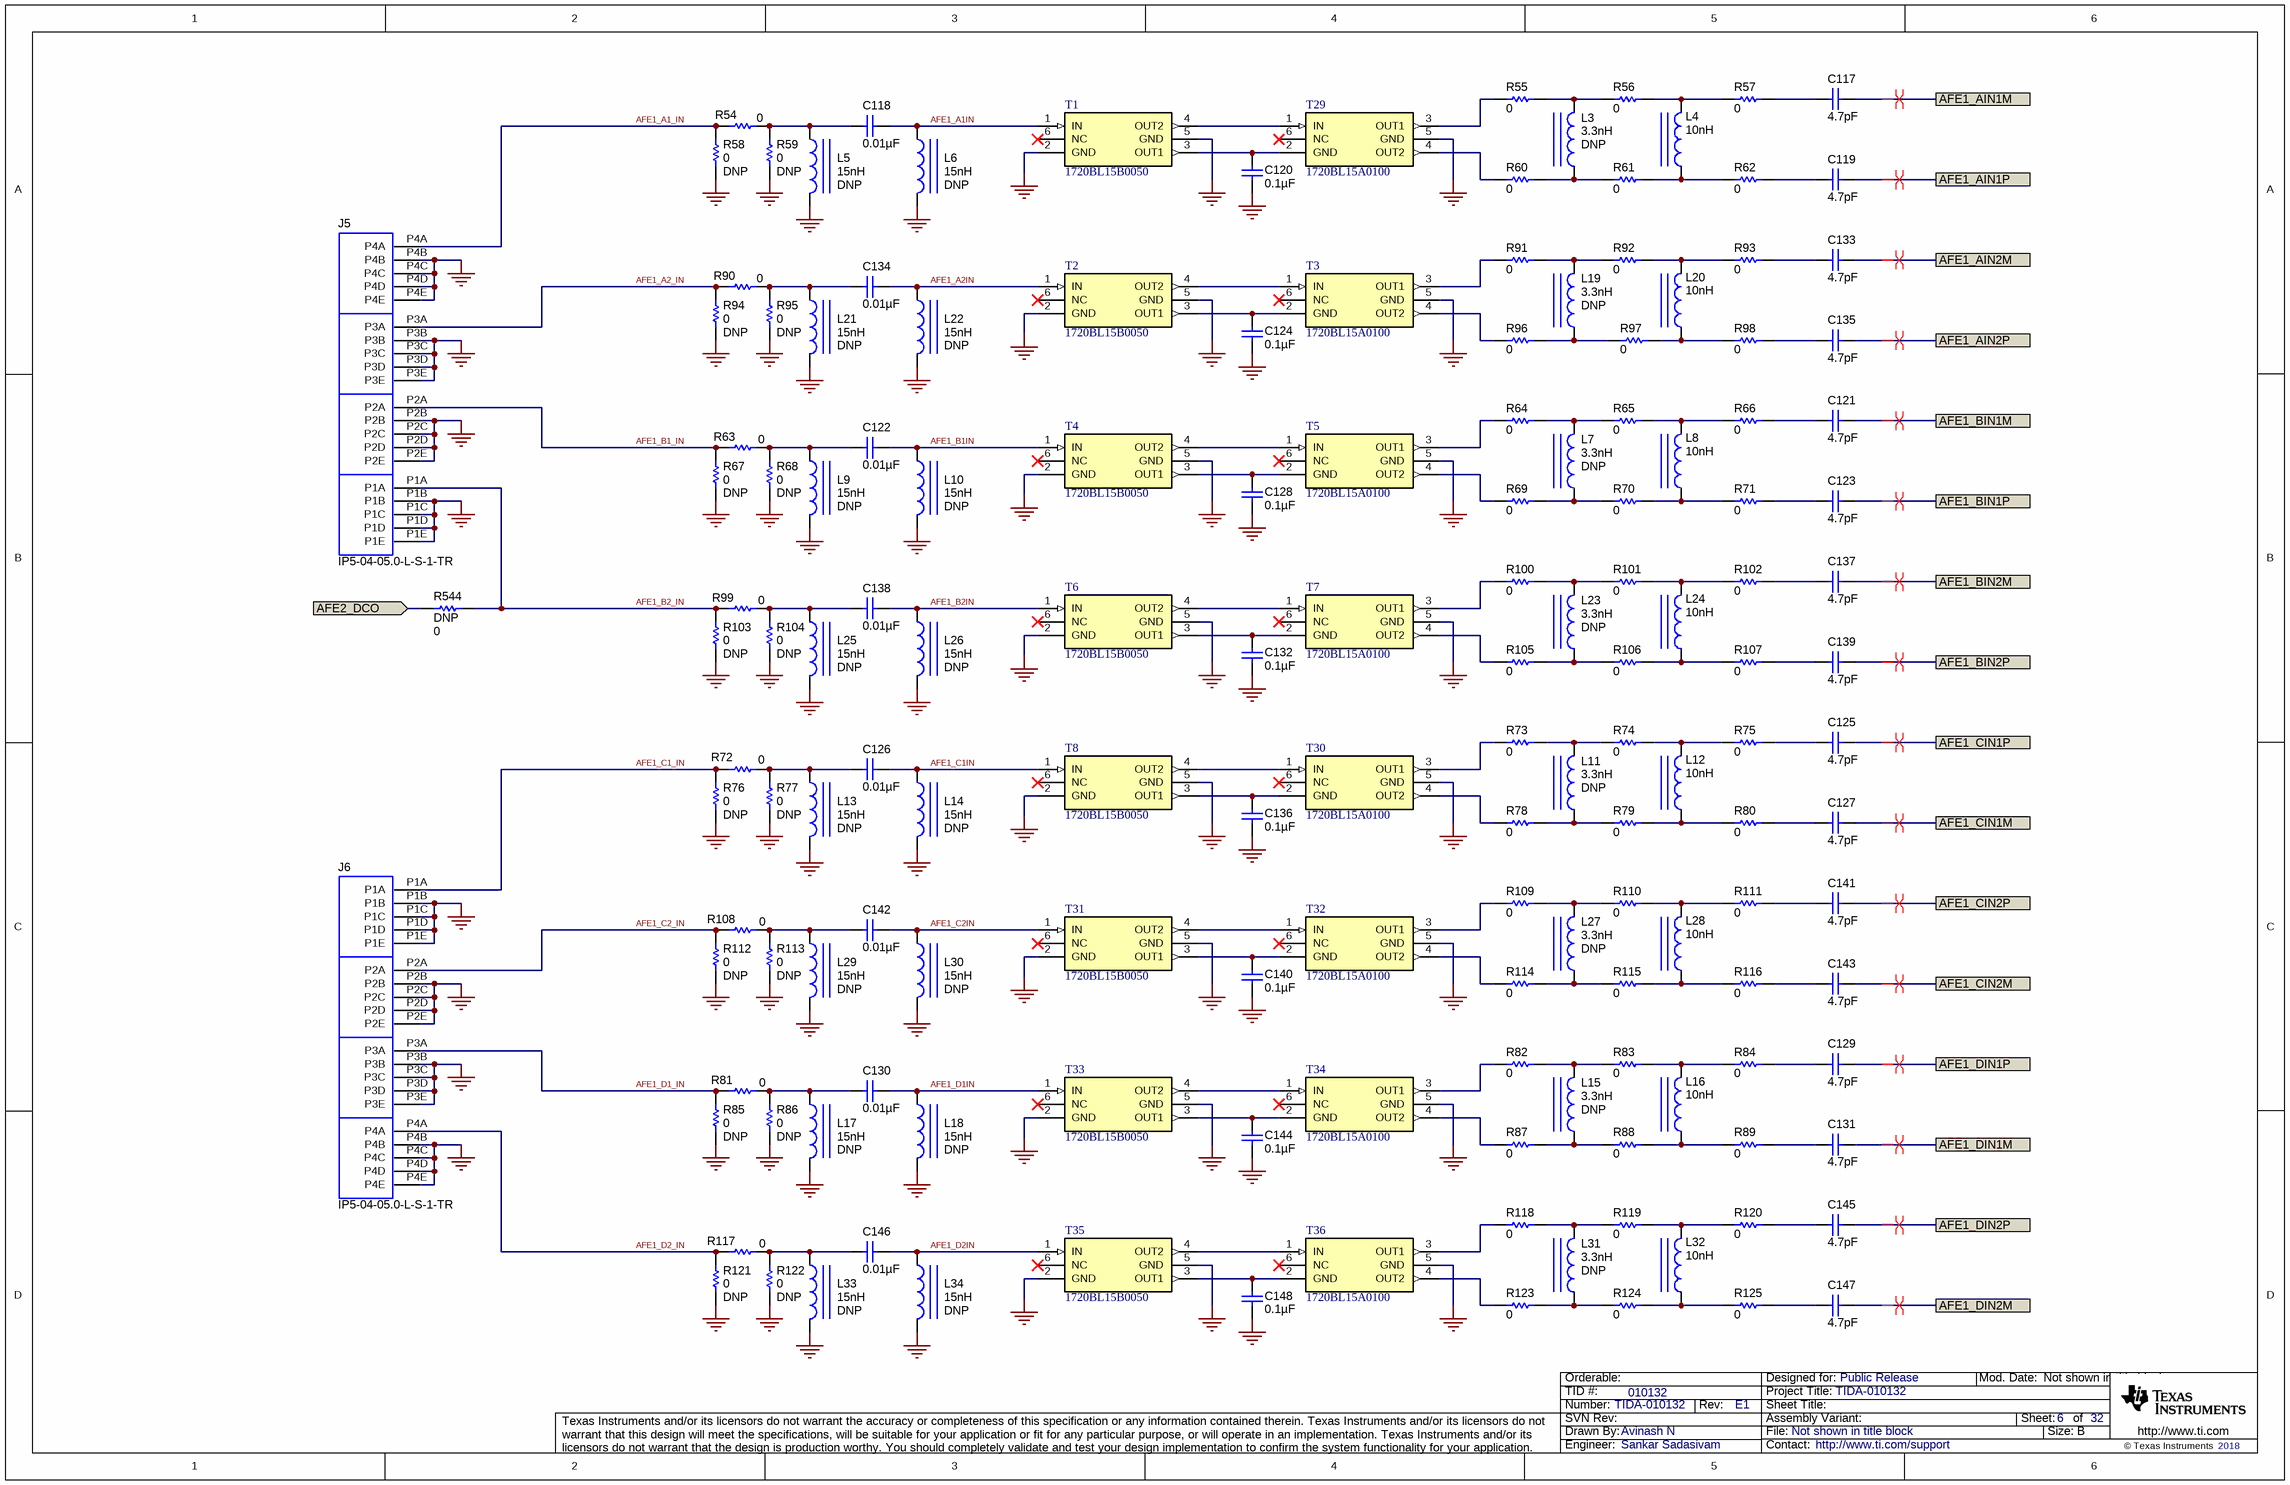
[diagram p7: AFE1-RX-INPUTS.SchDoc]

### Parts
C117  ValueDisplayed: 4.7pF  [0201]  (hidden comment: GRM0335C1H4R7CA01D)
C118  ValueDisplayed: 0.01µF  [0402]  (hidden comment: GRM155R71H103KA88D)
C119  ValueDisplayed: 4.7pF  [0201]  (hidden comment: GRM0335C1H4R7CA01D)
C120  ValueDisplayed: 0.1µF  [0201]  (hidden comment: GRM033C71A104KE14D)
C121  ValueDisplayed: 4.7pF  [0201]  (hidden comment: GRM0335C1H4R7CA01D)
C122  ValueDisplayed: 0.01µF  [0402]  (hidden comment: GRM155R71H103KA88D)
C123  ValueDisplayed: 4.7pF  [0201]  (hidden comment: GRM0335C1H4R7CA01D)
C124  ValueDisplayed: 0.1µF  [0201]  (hidden comment: GRM033C71A104KE14D)
C125  ValueDisplayed: 4.7pF  [0201]  (hidden comment: GRM0335C1H4R7CA01D)
C126  ValueDisplayed: 0.01µF  [0402]  (hidden comment: GRM155R71H103KA88D)
C127  ValueDisplayed: 4.7pF  [0201]  (hidden comment: GRM0335C1H4R7CA01D)
C128  ValueDisplayed: 0.1µF  [0201]  (hidden comment: GRM033C71A104KE14D)
C129  ValueDisplayed: 4.7pF  [0201]  (hidden comment: GRM0335C1H4R7CA01D)
C130  ValueDisplayed: 0.01µF  [0402]  (hidden comment: GRM155R71H103KA88D)
C131  ValueDisplayed: 4.7pF  [0201]  (hidden comment: GRM0335C1H4R7CA01D)
C132  ValueDisplayed: 0.1µF  [0201]  (hidden comment: GRM033C71A104KE14D)
C133  ValueDisplayed: 4.7pF  [0201]  (hidden comment: GRM0335C1H4R7CA01D)
C134  ValueDisplayed: 0.01µF  [0402]  (hidden comment: GRM155R71H103KA88D)
C135  ValueDisplayed: 4.7pF  [0201]  (hidden comment: GRM0335C1H4R7CA01D)
C136  ValueDisplayed: 0.1µF  [0201]  (hidden comment: GRM033C71A104KE14D)
C137  ValueDisplayed: 4.7pF  [0201]  (hidden comment: GRM0335C1H4R7CA01D)
C138  ValueDisplayed: 0.01µF  [0402]  (hidden comment: GRM155R71H103KA88D)
C139  ValueDisplayed: 4.7pF  [0201]  (hidden comment: GRM0335C1H4R7CA01D)
C140  ValueDisplayed: 0.1µF  [0201]  (hidden comment: GRM033C71A104KE14D)
C141  ValueDisplayed: 4.7pF  [0201]  (hidden comment: GRM0335C1H4R7CA01D)
C142  ValueDisplayed: 0.01µF  [0402]  (hidden comment: GRM155R71H103KA88D)
C143  ValueDisplayed: 4.7pF  [0201]  (hidden comment: GRM0335C1H4R7CA01D)
C144  ValueDisplayed: 0.1µF  [0201]  (hidden comment: GRM033C71A104KE14D)
C145  ValueDisplayed: 4.7pF  [0201]  (hidden comment: GRM0335C1H4R7CA01D)
C146  ValueDisplayed: 0.01µF  [0402]  (hidden comment: GRM155R71H103KA88D)
C147  ValueDisplayed: 4.7pF  [0201]  (hidden comment: GRM0335C1H4R7CA01D)
C148  ValueDisplayed: 0.1µF  [0201]  (hidden comment: GRM033C71A104KE14D)
J5  IP5-04-05.0-L-S-1-TR  [Samtec_IP5-04-05.0-X-S-X-TR]
J6  IP5-04-05.0-L-S-1-TR  [Samtec_IP5-04-05.0-X-S-X-TR]
L3  DNP  ValueDisplayed: 3.3nH  [IND_LQG15H]
L4  ValueDisplayed: 10nH  [IND_LQG15H]  (hidden comment: LQG15HS10NJ02D)
L5  DNP  ValueDisplayed: 15nH  [IND_LQG15H]
L6  DNP  ValueDisplayed: 15nH  [IND_LQG15H]
L7  DNP  ValueDisplayed: 3.3nH  [IND_LQG15H]
L8  ValueDisplayed: 10nH  [IND_LQG15H]  (hidden comment: LQG15HS10NJ02D)
L9  DNP  ValueDisplayed: 15nH  [IND_LQG15H]
L10  DNP  ValueDisplayed: 15nH  [IND_LQG15H]
L11  DNP  ValueDisplayed: 3.3nH  [IND_LQG15H]
L12  ValueDisplayed: 10nH  [IND_LQG15H]  (hidden comment: LQG15HS10NJ02D)
L13  DNP  ValueDisplayed: 15nH  [IND_LQG15H]
L14  DNP  ValueDisplayed: 15nH  [IND_LQG15H]
L15  DNP  ValueDisplayed: 3.3nH  [IND_LQG15H]
L16  ValueDisplayed: 10nH  [IND_LQG15H]  (hidden comment: LQG15HS10NJ02D)
L17  DNP  ValueDisplayed: 15nH  [IND_LQG15H]
L18  DNP  ValueDisplayed: 15nH  [IND_LQG15H]
L19  DNP  ValueDisplayed: 3.3nH  [IND_LQG15H]
L20  ValueDisplayed: 10nH  [IND_LQG15H]  (hidden comment: LQG15HS10NJ02D)
L21  DNP  ValueDisplayed: 15nH  [IND_LQG15H]
L22  DNP  ValueDisplayed: 15nH  [IND_LQG15H]
L23  DNP  ValueDisplayed: 3.3nH  [IND_LQG15H]
L24  ValueDisplayed: 10nH  [IND_LQG15H]  (hidden comment: LQG15HS10NJ02D)
L25  DNP  ValueDisplayed: 15nH  [IND_LQG15H]
L26  DNP  ValueDisplayed: 15nH  [IND_LQG15H]
L27  DNP  ValueDisplayed: 3.3nH  [IND_LQG15H]
L28  ValueDisplayed: 10nH  [IND_LQG15H]  (hidden comment: LQG15HS10NJ02D)
L29  DNP  ValueDisplayed: 15nH  [IND_LQG15H]
L30  DNP  ValueDisplayed: 15nH  [IND_LQG15H]
L31  DNP  ValueDisplayed: 3.3nH  [IND_LQG15H]
L32  ValueDisplayed: 10nH  [IND_LQG15H]  (hidden comment: LQG15HS10NJ02D)
L33  DNP  ValueDisplayed: 15nH  [IND_LQG15H]
L34  DNP  ValueDisplayed: 15nH  [IND_LQG15H]
R54  ValueDisplayed: 0  [0402]  (hidden comment: ERJ-2GE0R00X)
R55  ValueDisplayed: 0  [0201]  (hidden comment: ERJ-1GN0R00C)
R56  ValueDisplayed: 0  [0201]  (hidden comment: ERJ-1GN0R00C)
R57  ValueDisplayed: 0  [0201]  (hidden comment: ERJ-1GN0R00C)
R58  DNP  ValueDisplayed: 0  [0402]
R59  DNP  ValueDisplayed: 0  [0402]
R60  ValueDisplayed: 0  [0201]  (hidden comment: ERJ-1GN0R00C)
R61  ValueDisplayed: 0  [0201]  (hidden comment: ERJ-1GN0R00C)
R62  ValueDisplayed: 0  [0201]  (hidden comment: ERJ-1GN0R00C)
R63  ValueDisplayed: 0  [0402]  (hidden comment: ERJ-2GE0R00X)
R64  ValueDisplayed: 0  [0201]  (hidden comment: ERJ-1GN0R00C)
R65  ValueDisplayed: 0  [0201]  (hidden comment: ERJ-1GN0R00C)
R66  ValueDisplayed: 0  [0201]  (hidden comment: ERJ-1GN0R00C)
R67  DNP  ValueDisplayed: 0  [0402]
R68  DNP  ValueDisplayed: 0  [0402]
R69  ValueDisplayed: 0  [0201]  (hidden comment: ERJ-1GN0R00C)
R70  ValueDisplayed: 0  [0201]  (hidden comment: ERJ-1GN0R00C)
R71  ValueDisplayed: 0  [0201]  (hidden comment: ERJ-1GN0R00C)
R72  ValueDisplayed: 0  [0402]  (hidden comment: ERJ-2GE0R00X)
R73  ValueDisplayed: 0  [0201]  (hidden comment: ERJ-1GN0R00C)
R74  ValueDisplayed: 0  [0201]  (hidden comment: ERJ-1GN0R00C)
R75  ValueDisplayed: 0  [0201]  (hidden comment: ERJ-1GN0R00C)
R76  DNP  ValueDisplayed: 0  [0402]
R77  DNP  ValueDisplayed: 0  [0402]
R78  ValueDisplayed: 0  [0201]  (hidden comment: ERJ-1GN0R00C)
R79  ValueDisplayed: 0  [0201]  (hidden comment: ERJ-1GN0R00C)
R80  ValueDisplayed: 0  [0201]  (hidden comment: ERJ-1GN0R00C)
R81  ValueDisplayed: 0  [0402]  (hidden comment: ERJ-2GE0R00X)
R82  ValueDisplayed: 0  [0201]  (hidden comment: ERJ-1GN0R00C)
R83  ValueDisplayed: 0  [0201]  (hidden comment: ERJ-1GN0R00C)
R84  ValueDisplayed: 0  [0201]  (hidden comment: ERJ-1GN0R00C)
R85  DNP  ValueDisplayed: 0  [0402]
R86  DNP  ValueDisplayed: 0  [0402]
R87  ValueDisplayed: 0  [0201]  (hidden comment: ERJ-1GN0R00C)
R88  ValueDisplayed: 0  [0201]  (hidden comment: ERJ-1GN0R00C)
R89  ValueDisplayed: 0  [0201]  (hidden comment: ERJ-1GN0R00C)
R90  ValueDisplayed: 0  [0402]  (hidden comment: ERJ-2GE0R00X)
R91  ValueDisplayed: 0  [0201]  (hidden comment: ERJ-1GN0R00C)
R92  ValueDisplayed: 0  [0201]  (hidden comment: ERJ-1GN0R00C)
R93  ValueDisplayed: 0  [0201]  (hidden comment: ERJ-1GN0R00C)
R94  DNP  ValueDisplayed: 0  [0402]
R95  DNP  ValueDisplayed: 0  [0402]
R96  ValueDisplayed: 0  [0201]  (hidden comment: ERJ-1GN0R00C)
R97  ValueDisplayed: 0  [0201]  (hidden comment: ERJ-1GN0R00C)
R98  ValueDisplayed: 0  [0201]  (hidden comment: ERJ-1GN0R00C)
R99  ValueDisplayed: 0  [0402]  (hidden comment: ERJ-2GE0R00X)
R100  ValueDisplayed: 0  [0201]  (hidden comment: ERJ-1GN0R00C)
R101  ValueDisplayed: 0  [0201]  (hidden comment: ERJ-1GN0R00C)
R102  ValueDisplayed: 0  [0201]  (hidden comment: ERJ-1GN0R00C)
R103  DNP  ValueDisplayed: 0  [0402]
R104  DNP  ValueDisplayed: 0  [0402]
R105  ValueDisplayed: 0  [0201]  (hidden comment: ERJ-1GN0R00C)
R106  ValueDisplayed: 0  [0201]  (hidden comment: ERJ-1GN0R00C)
R107  ValueDisplayed: 0  [0201]  (hidden comment: ERJ-1GN0R00C)
R108  ValueDisplayed: 0  [0402]  (hidden comment: ERJ-2GE0R00X)
R109  ValueDisplayed: 0  [0201]  (hidden comment: ERJ-1GN0R00C)
R110  ValueDisplayed: 0  [0201]  (hidden comment: ERJ-1GN0R00C)
R111  ValueDisplayed: 0  [0201]  (hidden comment: ERJ-1GN0R00C)
R112  DNP  ValueDisplayed: 0  [0402]
R113  DNP  ValueDisplayed: 0  [0402]
R114  ValueDisplayed: 0  [0201]  (hidden comment: ERJ-1GN0R00C)
R115  ValueDisplayed: 0  [0201]  (hidden comment: ERJ-1GN0R00C)
R116  ValueDisplayed: 0  [0201]  (hidden comment: ERJ-1GN0R00C)
R117  ValueDisplayed: 0  [0402]  (hidden comment: ERJ-2GE0R00X)
R118  ValueDisplayed: 0  [0201]  (hidden comment: ERJ-1GN0R00C)
R119  ValueDisplayed: 0  [0201]  (hidden comment: ERJ-1GN0R00C)
R120  ValueDisplayed: 0  [0201]  (hidden comment: ERJ-1GN0R00C)
R121  DNP  ValueDisplayed: 0  [0402]
R122  DNP  ValueDisplayed: 0  [0402]
R123  ValueDisplayed: 0  [0201]  (hidden comment: ERJ-1GN0R00C)
R124  ValueDisplayed: 0  [0201]  (hidden comment: ERJ-1GN0R00C)
R125  ValueDisplayed: 0  [0201]  (hidden comment: ERJ-1GN0R00C)
R544  DNP  ValueDisplayed: 0  [0402]
T1  1720BL15B0050
T2  1720BL15B0050
T3  1720BL15A0100
T4  1720BL15B0050
T5  1720BL15A0100
T6  1720BL15B0050
T7  1720BL15A0100
T8  1720BL15B0050
T29  1720BL15A0100
T30  1720BL15A0100
T31  1720BL15B0050
T32  1720BL15A0100
T33  1720BL15B0050
T34  1720BL15A0100
T35  1720BL15B0050
T36  1720BL15A0100

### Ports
AFE1_AIN1M, AFE1_AIN1P, AFE1_AIN2M, AFE1_AIN2P, AFE1_BIN1M, AFE1_BIN1P, AFE1_BIN2M, AFE1_BIN2P, AFE1_CIN1M, AFE1_CIN1P, AFE1_CIN2M, AFE1_CIN2P, AFE1_DIN1M, AFE1_DIN1P, AFE1_DIN2M, AFE1_DIN2P, AFE2_DCO (in)

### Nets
GND: C120.2 C124.2 C128.2 C132.2 C136.2 C140.2 C144.2 C148.2 J5.P1B J5.P1C J5.P1D J5.P1E J5.P2B J5.P2C J5.P2D J5.P2E J5.P3B J5.P3C J5.P3D J5.P3E J5.P4B J5.P4C J5.P4D J5.P4E J6.P1B J6.P1C J6.P1D J6.P1E J6.P2B J6.P2C J6.P2D J6.P2E J6.P3B J6.P3C J6.P3D J6.P3E J6.P4B J6.P4C J6.P4D J6.P4E L5.2 L6.2 L9.2 L10.2 L13.2 L14.2 L17.2 L18.2 L21.2 L22.2 L25.2 L26.2 L29.2 L30.2 L33.2 L34.2 R58.1 R59.1 R67.1 R68.1 R76.1 R77.1 R85.1 R86.1 R94.1 R95.1 R103.1 R104.1 R112.1 R113.1 R121.1 R122.1 T1.2(GND) T1.5(GND) T2.2(GND) T2.5(GND) T3.5(GND) T4.2(GND) T4.5(GND) T5.5(GND) T6.2(GND) T6.5(GND) T7.5(GND) T8.2(GND) T8.5(GND) T29.5(GND) T30.5(GND) T31.2(GND) T31.5(GND) T32.5(GND) T33.2(GND) T33.5(GND) T34.5(GND) T35.2(GND) T35.5(GND) T36.5(GND)
AFE1_A1_IN: J5.P4A R54.1 R58.2
AFE1_A1IN: C118.1 L6.1 T1.1(IN)
AFE1_A2_IN: J5.P3A R90.1 R94.2
AFE1_A2IN: C134.1 L22.1 T2.1(IN)
AFE1_AIN1M: C117.1 ; port AFE1_AIN1M
AFE1_AIN1P: C119.1 ; port AFE1_AIN1P
AFE1_AIN2M: C133.1 ; port AFE1_AIN2M
AFE1_AIN2P: C135.1 ; port AFE1_AIN2P
AFE1_B1_IN: J5.P2A R63.1 R67.2
AFE1_B1IN: C122.1 L10.1 T4.1(IN)
AFE1_B2_IN: J5.P1A R99.1 R103.2 R544.1
AFE1_B2IN: C138.1 L26.1 T6.1(IN)
AFE1_BIN1M: C121.1 ; port AFE1_BIN1M
AFE1_BIN1P: C123.1 ; port AFE1_BIN1P
AFE1_BIN2M: C137.1 ; port AFE1_BIN2M
AFE1_BIN2P: C139.1 ; port AFE1_BIN2P
AFE1_C1_IN: J6.P1A R72.1 R76.2
AFE1_C1IN: C126.1 L14.1 T8.1(IN)
AFE1_C2_IN: J6.P2A R108.1 R112.2
AFE1_C2IN: C142.1 L30.1 T31.1(IN)
AFE1_CIN1M: C127.1 ; port AFE1_CIN1M
AFE1_CIN1P: C125.1 ; port AFE1_CIN1P
AFE1_CIN2M: C143.1 ; port AFE1_CIN2M
AFE1_CIN2P: C141.1 ; port AFE1_CIN2P
AFE1_D1_IN: J6.P3A R81.1 R85.2
AFE1_D1IN: C130.1 L18.1 T33.1(IN)
AFE1_D2_IN: J6.P4A R117.1 R121.2
AFE1_D2IN: C146.1 L34.1 T35.1(IN)
AFE1_DIN1M: C131.1 ; port AFE1_DIN1M
AFE1_DIN1P: C129.1 ; port AFE1_DIN1P
AFE1_DIN2M: C147.1 ; port AFE1_DIN2M
AFE1_DIN2P: C145.1 ; port AFE1_DIN2P
AFE2_DCO: R544.2 ; port AFE2_DCO
NetC117_2: C117.2 R57.2
NetC118_2: C118.2 L5.1 R54.2 R59.2
NetC119_2: C119.2 R62.2
NetC120_1: C120.1 T1.3(OUT1) T29.2(GND)
NetC121_2: C121.2 R66.2
NetC122_2: C122.2 L9.1 R63.2 R68.2
NetC123_2: C123.2 R71.2
NetC124_1: C124.1 T2.3(OUT1) T3.2(GND)
NetC125_2: C125.2 R75.2
NetC126_2: C126.2 L13.1 R72.2 R77.2
NetC127_2: C127.2 R80.2
NetC128_1: C128.1 T4.3(OUT1) T5.2(GND)
NetC129_2: C129.2 R84.2
NetC130_2: C130.2 L17.1 R81.2 R86.2
NetC131_2: C131.2 R89.2
NetC132_1: C132.1 T6.3(OUT1) T7.2(GND)
NetC133_2: C133.2 R93.2
NetC134_2: C134.2 L21.1 R90.2 R95.2
NetC135_2: C135.2 R98.2
NetC136_1: C136.1 T8.3(OUT1) T30.2(GND)
NetC137_2: C137.2 R102.2
NetC138_2: C138.2 L25.1 R99.2 R104.2
NetC139_2: C139.2 R107.2
NetC140_1: C140.1 T31.3(OUT1) T32.2(GND)
NetC141_2: C141.2 R111.2
NetC142_2: C142.2 L29.1 R108.2 R113.2
NetC143_2: C143.2 R116.2
NetC144_1: C144.1 T33.3(OUT1) T34.2(GND)
NetC145_2: C145.2 R120.2
NetC146_2: C146.2 L33.1 R117.2 R122.2
NetC147_2: C147.2 R125.2
NetC148_1: C148.1 T35.3(OUT1) T36.2(GND)
NetL3_1: L3.1 R60.2 R61.1
NetL3_2: L3.2 R55.2 R56.1
NetL4_1: L4.1 R61.2 R62.1
NetL4_2: L4.2 R56.2 R57.1
NetL7_1: L7.1 R69.2 R70.1
NetL7_2: L7.2 R64.2 R65.1
NetL8_1: L8.1 R70.2 R71.1
NetL8_2: L8.2 R65.2 R66.1
NetL11_1: L11.1 R78.2 R79.1
NetL11_2: L11.2 R73.2 R74.1
NetL12_1: L12.1 R79.2 R80.1
NetL12_2: L12.2 R74.2 R75.1
NetL15_1: L15.1 R87.2 R88.1
NetL15_2: L15.2 R82.2 R83.1
NetL16_1: L16.1 R88.2 R89.1
NetL16_2: L16.2 R83.2 R84.1
NetL19_1: L19.1 R96.2 R97.1
NetL19_2: L19.2 R91.2 R92.1
NetL20_1: L20.1 R97.2 R98.1
NetL20_2: L20.2 R92.2 R93.1
NetL23_1: L23.1 R105.2 R106.1
NetL23_2: L23.2 R100.2 R101.1
NetL24_1: L24.1 R106.2 R107.1
NetL24_2: L24.2 R101.2 R102.1
NetL27_1: L27.1 R114.2 R115.1
NetL27_2: L27.2 R109.2 R110.1
NetL28_1: L28.1 R115.2 R116.1
NetL28_2: L28.2 R110.2 R111.1
NetL31_1: L31.1 R123.2 R124.1
NetL31_2: L31.2 R118.2 R119.1
NetL32_1: L32.1 R124.2 R125.1
NetL32_2: L32.2 R119.2 R120.1
NetR55_1: R55.1 T29.3(OUT1)
NetR60_1: R60.1 T29.4(OUT2)
NetR64_1: R64.1 T5.3(OUT1)
NetR69_1: R69.1 T5.4(OUT2)
NetR73_1: R73.1 T30.3(OUT1)
NetR78_1: R78.1 T30.4(OUT2)
NetR82_1: R82.1 T34.3(OUT1)
NetR87_1: R87.1 T34.4(OUT2)
NetR91_1: R91.1 T3.3(OUT1)
NetR96_1: R96.1 T3.4(OUT2)
NetR100_1: R100.1 T7.3(OUT1)
NetR105_1: R105.1 T7.4(OUT2)
NetR109_1: R109.1 T32.3(OUT1)
NetR114_1: R114.1 T32.4(OUT2)
NetR118_1: R118.1 T36.3(OUT1)
NetR123_1: R123.1 T36.4(OUT2)
NetT1_4: T1.4(OUT2) T29.1(IN)
NetT2_4: T2.4(OUT2) T3.1(IN)
NetT4_4: T4.4(OUT2) T5.1(IN)
NetT6_4: T6.4(OUT2) T7.1(IN)
NetT8_4: T8.4(OUT2) T30.1(IN)
NetT31_4: T31.4(OUT2) T32.1(IN)
NetT33_4: T33.4(OUT2) T34.1(IN)
NetT35_4: T35.4(OUT2) T36.1(IN)

Not connected (* = marked no-connect by the designer): T1 6(NC)*; T2 6(NC)*; T3 6(NC)*; T4 6(NC)*; T5 6(NC)*; T6 6(NC)*; T7 6(NC)*; T8 6(NC)*; T29 6(NC)*; T30 6(NC)*; T31 6(NC)*; T32 6(NC)*; T33 6(NC)*; T34 6(NC)*; T35 6(NC)*; T36 6(NC)*

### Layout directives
differential pair: AFE1_AIN1M, AFE1_AIN1P, AFE1_AIN2M, AFE1_AIN2P, AFE1_BIN1M, AFE1_BIN1P, AFE1_BIN2M, AFE1_BIN2P, AFE1_CIN1M, AFE1_CIN1P, AFE1_CIN2M, AFE1_CIN2P, AFE1_DIN1M, AFE1_DIN1P, AFE1_DIN2M, AFE1_DIN2P

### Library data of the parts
C117 C119 C121 C123 C125 C127 C129 C131 C133 C135 C137 C139 C141 C143 C145 C147 = GRM0335C1H4R7CA01D: CAP, CERM, 4.7 pF, 50 V,+/- 5%, C0G/NP0, 0201; Manufacturer: MuRata; Polarized: N; CompType: Capacitor; Value: 4.7pF; U/M: EA; Cap_F: 0.0000000000047; Tolerance_%: 5; Value1: Unknown; VDC_V: 50; Value2: 50V; TaMin_C: -55; TaMax_C: 125; SizeArea_mm2: 0.18; SizeAreaWB_mm2: 2.08; SizeX_mm: 0.6; SizeY_mm: 0.3; SizeZ_mm: 0.26; AEC Category: Q200
C118 C122 C126 C130 C134 C138 C142 C146 = GRM155R71H103KA88D: CAP, CERM, 0.01 µF, 50 V,+/- 10%, X7R, 0402; Manufacturer: MuRata; Polarized: N; CompType: Capacitor; Value: 0.01uF; U/M: EA; Cap_F: 0.00000001; Tolerance_%: 10; Value1: Unknown; VDC_V: 50; Value2: 50V; TaMin_C: -55; TaMax_C: 125; SizeArea_mm2: 0.5; SizeAreaWB_mm2: 3; SizeX_mm: 1; SizeZ_mm: 0.6; AEC Category: Q200; Green_Lifecycle: Active; Green_REACh: Passed
C120 C124 C128 C132 C136 C140 C144 C148 = GRM033C71A104KE14D: CAP, CERM, 0.1 µF, 10 V,+/- 10%, X7S, 0201; Manufacturer: MuRata; Polarized: N; CompType: Capacitor; Value: 0.1uF; U/M: EA; Cap_F: 0.0000001; Tolerance_%: 10; Value1: Unknown; Value2: 10V; TaMin_C: -55; TaMax_C: 125; SizeArea_mm2: 0.18; SizeAreaWB_mm2: 2.08; SizeX_mm: 0.6; SizeY_mm: 0.3; SizeZ_mm: 0.26; AEC Category: Q200
J5 J6 = CMP-0084573-1: Plug, 4 Ports, TH; Manufacturer: Samtec; Gender: Male; Voltage_V: 200V; ContactFinish: Gold; Row_Count: 1; Current_A: 2.36A; Cert_UL: Y
L3 L7 L11 L15 L19 L23 L27 L31 = LQG15HS3N3S02D: Inductor, Multilayer, Air Core, 3.3 nH, 0.3 A, 0.17 ohm, SMD; Manufacturer: MuRata; Value: 3.3nH; Ind_H: 3.3E-9; Imax_A: 0.3; Irms: 0.3A @ C rise; Isat: 0.3A @ % inductance drop; DCR_ohm: 0.17; Value2: 0.3A; SizeAreaWB_mm2: 3; SizeArea_mm2: 0.5; SizeX_mm: 1; SizeZ_mm: 0.55; AEC Category: Q200; Green_Lifecycle: Active; Green_REACh: Passed
L4 L8 L12 L16 L20 L24 L28 L32 = LQG15HS10NJ02D: Inductor, Multilayer, Air Core, 10 nH, 0.3 A, 0.26 ohm, SMD; Manufacturer: MuRata; Value: 10nH; Ind_H: 10.0E-9; Imax_A: 0.3; Irms: 0.3A @ C rise; Isat: 0.3A @ % inductance drop; DCR_ohm: 0.26; Value2: 0.3A; SizeAreaWB_mm2: 3; SizeArea_mm2: 0.5; SizeX_mm: 1; SizeZ_mm: 0.55; AEC Category: Q200; Green_Lifecycle: Active; Green_REACh: Passed
L5 L6 L9 L10 L13 L14 L17 L18 L21 L22 L25 L26 L29 L30 L33 L34 = LQG15HS15NJ02D: Inductor, Multilayer, Air Core, 15 nH, 0.3 A, 0.32 ohm, SMD; Manufacturer: MuRata; Value: 15nH; Ind_H: 15.0E-9; Imax_A: 0.3; Irms: 0.3A @ C rise; Isat: 0.3A @ % inductance drop; DCR_ohm: 0.32; Value2: 0.3A; SizeAreaWB_mm2: 3; SizeArea_mm2: 0.5; SizeX_mm: 1; SizeZ_mm: 0.55; AEC Category: Q200; Green_Lifecycle: Active; Green_REACh: Passed
R54 R58 R59 R63 R67 R68 R72 R76 R77 R81 R85 R86 R90 R94 R95 R99 R103 R104 R108 R112 R113 R117 R121 R122 R544 = ERJ-2GE0R00X: RES, 0, 5%, 0.063 W, 0402; Manufacturer: Panasonic; CompType: Resistor; Value: 0; Value_Code: 0000; Tolerance_%: 5; Power_W: 0.063; Value2: 0.063W; VDC_V: 50; TempCo: 600 ppm/C; SizeArea_mm2: 0.5; SizeX_mm: 1; SizeZ_mm: 0.6; EIA_Code: E24; U/M: EA; AEC Category: Q200; Green_Lifecycle: Active; Green_REACh: Passed
R55-R57 R60-R62 R64-R66 R69-R71 R73-R75 R78-R80 R82-R84 R87-R89 R91-R93 R96-R98 R100-R102 R105-R107 R109-R111 R114-R116 R118-R120 R123-R125 = ERJ-1GN0R00C: RES, 0, 5%, 0.05 W, AEC-Q200 Grade 0, 0201; Manufacturer: Panasonic; CompType: Resistor; Value: 0; Value_Code: 0000; Tolerance_%: 5; Power_W: 0.05; Value2: 0.05W; TempCo: ppm/C; SizeArea_mm2: 0.18; SizeX_mm: 0.6; SizeY_mm: 0.3; SizeZ_mm: 0.26; EIA_Code: E24; U/M: EA; AEC Category: Q200; AEC Qualified: Y
T1 T2 T4 T6 T8 T31 T33 T35 = 1720BL15B0050: BALUN 625MHZ-2.8GHZ 50/50 0805; PartNumber: 1720BL15B0050E; Manufacturer: Johanson Technology Inc.
T3 T5 T7 T29 T30 T32 T34 T36 = 1720BL15A0100: BALUN 625MHZ-2.8GHZ 50/100 0805; PartNumber: 1720BL15A0100E; Manufacturer: Johanson Technology Inc.

## Sheet AFE1-TX-OUTPUTS.SchDoc
size 431 x 279 mm; Date: Not shown in title block; ApprovedBy: Not shown in title block; CheckedBy: Not shown in title block; Author: Not shown in title block; CompanyName: Not shown in title block; DrawnBy: Avinash N; Engineer: Not shown in title block; Organization: Not shown in title block; Address1: Not shown in title block; Address2: Not shown in title block; Address3: Not shown in title block; Address4: Not shown in title block; DocumentNumber: 1; Revision: Use project parameter SCH_Rev; SheetNumber: 7; SheetTotal: 32; PageSetup: Record=PageOptions¦CenterHorizontal=True¦CenterVertical=True¦PrintScale=1.00¦XCorrection=1.00¦YCorrection=1.00¦PrintKind=0¦BorderSize=5000000¦LeftOffset=0¦BottomOffset=0¦Orientation=2¦PaperLength=1000¦PaperWidth=1000¦Scale=100¦PaperSource=15¦PrintQuality=600¦MediaType=1¦DitherType=10¦PaperKind=Letter¦PrintScaleMode=1
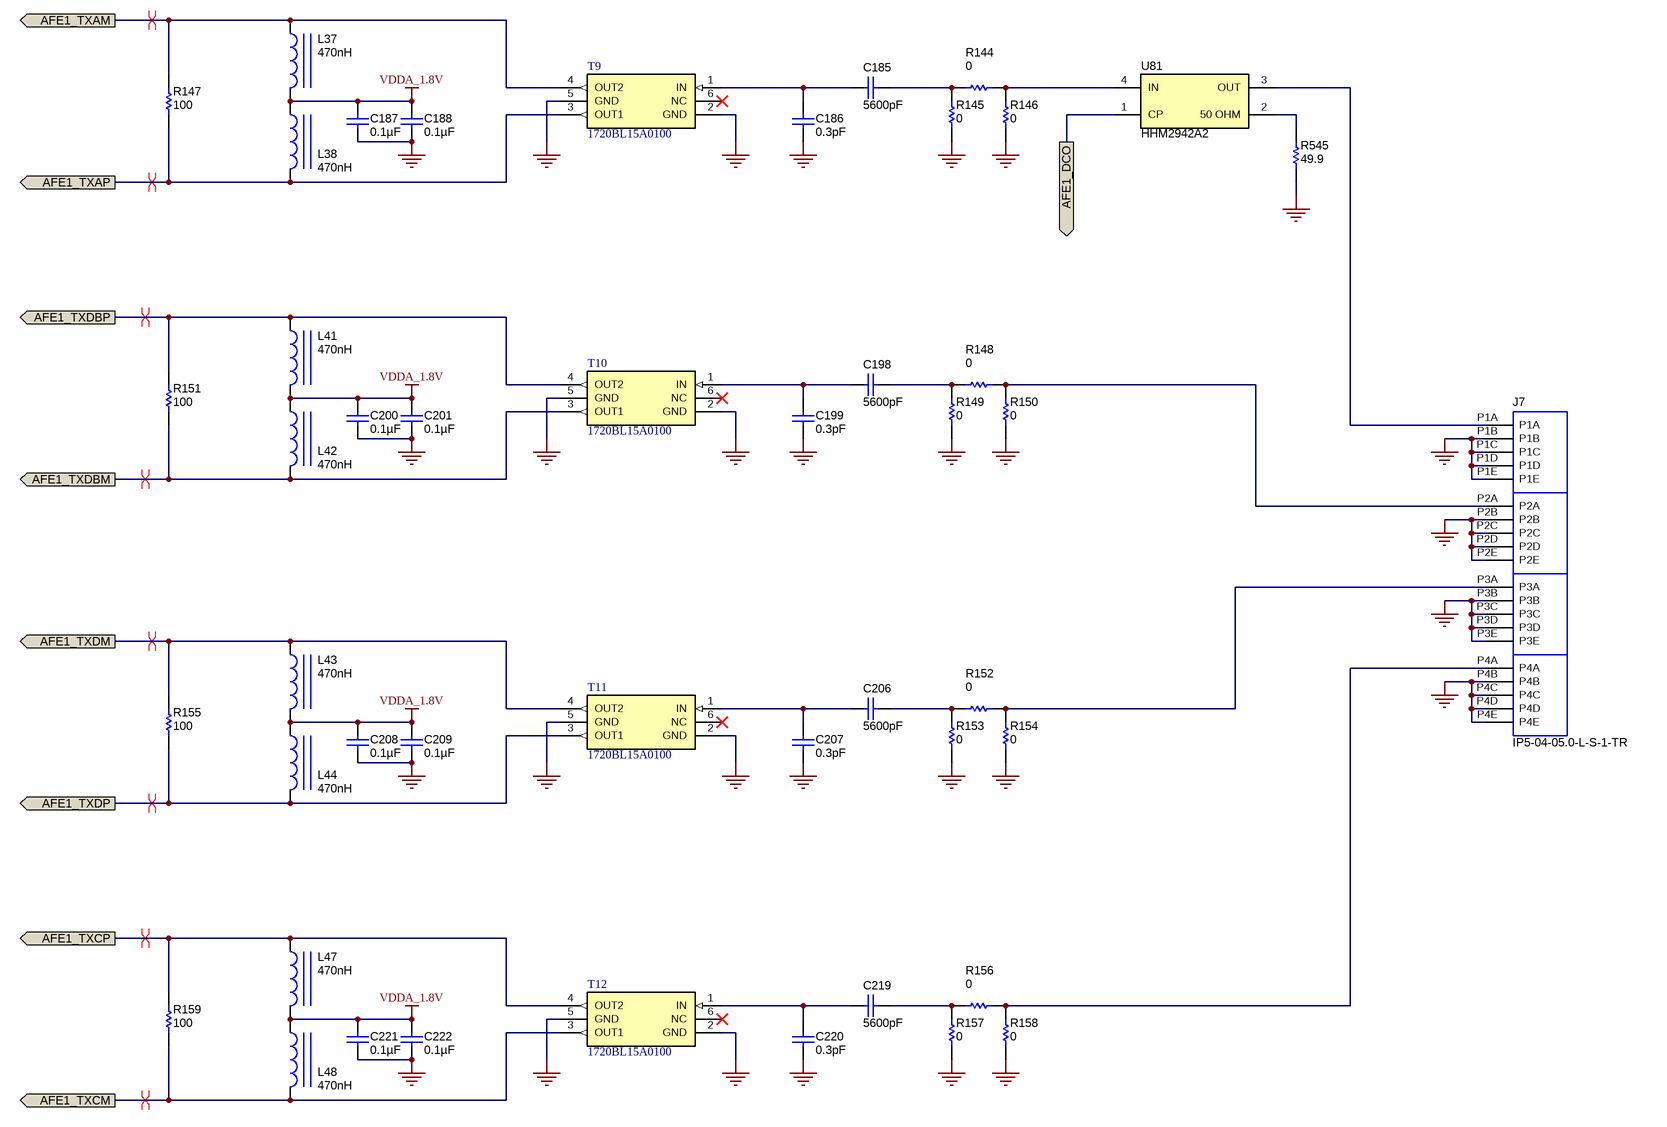
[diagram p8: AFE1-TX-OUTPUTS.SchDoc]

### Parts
C185  ValueDisplayed: 5600pF  [0402]  (hidden comment: GRM155R71H562KA88D)
C186  ValueDisplayed: 0.3pF  [0402]  (hidden comment: 500R07S0R3BV4T)
C187  ValueDisplayed: 0.1µF  [0201]  (hidden comment: GRM033C71A104KE14D)
C188  ValueDisplayed: 0.1µF  [0201]  (hidden comment: GRM033C71A104KE14D)
C198  ValueDisplayed: 5600pF  [0402]  (hidden comment: GRM155R71H562KA88D)
C199  ValueDisplayed: 0.3pF  [0402]  (hidden comment: 500R07S0R3BV4T)
C200  ValueDisplayed: 0.1µF  [0201]  (hidden comment: GRM033C71A104KE14D)
C201  ValueDisplayed: 0.1µF  [0201]  (hidden comment: GRM033C71A104KE14D)
C206  ValueDisplayed: 5600pF  [0402]  (hidden comment: GRM155R71H562KA88D)
C207  ValueDisplayed: 0.3pF  [0402]  (hidden comment: 500R07S0R3BV4T)
C208  ValueDisplayed: 0.1µF  [0201]  (hidden comment: GRM033C71A104KE14D)
C209  ValueDisplayed: 0.1µF  [0201]  (hidden comment: GRM033C71A104KE14D)
C219  ValueDisplayed: 5600pF  [0402]  (hidden comment: GRM155R71H562KA88D)
C220  ValueDisplayed: 0.3pF  [0402]  (hidden comment: 500R07S0R3BV4T)
C221  ValueDisplayed: 0.1µF  [0201]  (hidden comment: GRM033C71A104KE14D)
C222  ValueDisplayed: 0.1µF  [0201]  (hidden comment: GRM033C71A104KE14D)
J7  IP5-04-05.0-L-S-1-TR  [Samtec_IP5-04-05.0-X-S-X-TR]
L37  ValueDisplayed: 470nH  [DFE160808S]  (hidden comment: DFE160808S-R47M=P2)
L38  ValueDisplayed: 470nH  [DFE160808S]  (hidden comment: DFE160808S-R47M=P2)
L41  ValueDisplayed: 470nH  [DFE160808S]  (hidden comment: DFE160808S-R47M=P2)
L42  ValueDisplayed: 470nH  [DFE160808S]  (hidden comment: DFE160808S-R47M=P2)
L43  ValueDisplayed: 470nH  [DFE160808S]  (hidden comment: DFE160808S-R47M=P2)
L44  ValueDisplayed: 470nH  [DFE160808S]  (hidden comment: DFE160808S-R47M=P2)
L47  ValueDisplayed: 470nH  [DFE160808S]  (hidden comment: DFE160808S-R47M=P2)
L48  ValueDisplayed: 470nH  [DFE160808S]  (hidden comment: DFE160808S-R47M=P2)
R144  ValueDisplayed: 0  [0402]  (hidden comment: ERJ-2GE0R00X)
R145  ValueDisplayed: 0  [0402]  (hidden comment: ERJ-2GE0R00X)
R146  ValueDisplayed: 0  [0402]  (hidden comment: ERJ-2GE0R00X)
R147  ValueDisplayed: 100  [0402]  (hidden comment: ERJ-2RKF1000X)
R148  ValueDisplayed: 0  [0402]  (hidden comment: ERJ-2GE0R00X)
R149  ValueDisplayed: 0  [0402]  (hidden comment: ERJ-2GE0R00X)
R150  ValueDisplayed: 0  [0402]  (hidden comment: ERJ-2GE0R00X)
R151  ValueDisplayed: 100  [0402]  (hidden comment: ERJ-2RKF1000X)
R152  ValueDisplayed: 0  [0402]  (hidden comment: ERJ-2GE0R00X)
R153  ValueDisplayed: 0  [0402]  (hidden comment: ERJ-2GE0R00X)
R154  ValueDisplayed: 0  [0402]  (hidden comment: ERJ-2GE0R00X)
R155  ValueDisplayed: 100  [0402]  (hidden comment: ERJ-2RKF1000X)
R156  ValueDisplayed: 0  [0402]  (hidden comment: ERJ-2GE0R00X)
R157  ValueDisplayed: 0  [0402]  (hidden comment: ERJ-2GE0R00X)
R158  ValueDisplayed: 0  [0402]  (hidden comment: ERJ-2GE0R00X)
R159  ValueDisplayed: 100  [0402]  (hidden comment: ERJ-2RKF1000X)
R545  ValueDisplayed: 49.9  [0402]  (hidden comment: ERJ-2RKF49R9X)
T9  1720BL15A0100
T10  1720BL15A0100
T11  1720BL15A0100
T12  1720BL15A0100
U81  HHM2942A2  [HHM2942A2]

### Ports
AFE1_DCO (out), AFE1_TXAM (out), AFE1_TXAP (out), AFE1_TXCM (out), AFE1_TXCP (out), AFE1_TXDBM (out), AFE1_TXDBP (out), AFE1_TXDM (out), AFE1_TXDP (out)

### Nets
GND: C186.2 C187.1 C188.1 C199.2 C200.1 C201.1 C207.2 C208.1 C209.1 C220.2 C221.1 C222.1 J7.P1B J7.P1C J7.P1D J7.P1E J7.P2B J7.P2C J7.P2D J7.P2E J7.P3B J7.P3C J7.P3D J7.P3E J7.P4B J7.P4C J7.P4D J7.P4E R145.1 R146.1 R149.1 R150.1 R153.1 R154.1 R157.1 R158.1 R545.1 T9.2(GND) T9.5(GND) T10.2(GND) T10.5(GND) T11.2(GND) T11.5(GND) T12.2(GND) T12.5(GND)
VDDA_1.8V: C187.2 C188.2 C200.2 C201.2 C208.2 C209.2 C221.2 C222.2 L37.2 L38.1 L41.2 L42.1 L43.2 L44.1 L47.2 L48.1
AFE1_DCO: U81.1(CP) ; port AFE1_DCO
AFE1_TXAM: L37.1 R147.2 T9.4(OUT2) ; port AFE1_TXAM
AFE1_TXAP: L38.2 R147.1 T9.3(OUT1) ; port AFE1_TXAP
AFE1_TXCM: L48.2 R159.1 T12.3(OUT1) ; port AFE1_TXCM
AFE1_TXCP: L47.1 R159.2 T12.4(OUT2) ; port AFE1_TXCP
AFE1_TXDBM: L42.2 R151.1 T10.3(OUT1) ; port AFE1_TXDBM
AFE1_TXDBP: L41.1 R151.2 T10.4(OUT2) ; port AFE1_TXDBP
AFE1_TXDM: L43.1 R155.2 T11.4(OUT2) ; port AFE1_TXDM
AFE1_TXDP: L44.2 R155.1 T11.3(OUT1) ; port AFE1_TXDP
NetC185_1: C185.1 C186.1 T9.1(IN)
NetC185_2: C185.2 R144.1 R145.2
NetC198_1: C198.1 C199.1 T10.1(IN)
NetC198_2: C198.2 R148.1 R149.2
NetC206_1: C206.1 C207.1 T11.1(IN)
NetC206_2: C206.2 R152.1 R153.2
NetC219_1: C219.1 C220.1 T12.1(IN)
NetC219_2: C219.2 R156.1 R157.2
NetJ7_P1A: J7.P1A U81.3(OUT)
NetJ7_P2A: J7.P2A R148.2 R150.2
NetJ7_P3A: J7.P3A R152.2 R154.2
NetJ7_P4A: J7.P4A R156.2 R158.2
NetR144_2: R144.2 R146.2 U81.4(IN)
NetR545_2: R545.2 U81.2(50_OHM)

Not connected (* = marked no-connect by the designer): T9 6(NC)*; T10 6(NC)*; T11 6(NC)*; T12 6(NC)*

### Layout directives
differential pair: AFE1_TXAM, AFE1_TXAP, AFE1_TXCM, AFE1_TXCP, AFE1_TXDBM, AFE1_TXDBP, AFE1_TXDM, AFE1_TXDP

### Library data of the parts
C185 C198 C206 C219 = GRM155R71H562KA88D: CAP, CERM, 5600 pF, 50 V,+/- 10%, X7R, 0402; Manufacturer: MuRata; Polarized: N; CompType: Capacitor; Value: 5600pF; U/M: EA; Cap_F: 0.0000000056; Tolerance_%: 10; Value1: Unknown; VDC_V: 50; Value2: 50V; TaMin_C: -55; TaMax_C: 125; SizeArea_mm2: 0.5; SizeAreaWB_mm2: 3; SizeX_mm: 1; SizeZ_mm: 0.6; AEC Category: Q200; Green_Lifecycle: Active; Green_REACh: Passed
C186 C199 C207 C220 = 500R07S0R3BV4T: CAP, CERM, 0.3 pF, 50 V,+/- 30%, C0G/NP0, 0402; Manufacturer: Johanson Technology; Polarized: N; CompType: Capacitor; Value: 0.3pF; U/M: EA; Cap_F: 0.0000000000003; Tolerance_%: 30; Value1: Unknown; VDC_V: 50; Value2: 50V; TaMin_C: -55; TaMax_C: 125; SizeArea_mm2: 0.5; SizeAreaWB_mm2: 3; SizeX_mm: 1; SizeZ_mm: 0.6; AEC Category: Q200
C187 C188 C200 C201 C208 C209 C221 C222 = GRM033C71A104KE14D: as C120 on sheet AFE1-RX-INPUTS
J7 = CMP-0084573-1: as J5 on sheet AFE1-RX-INPUTS
L37 L38 L41-L44 L47 L48 = DFE160808S-R47M=P2: Inductor, Shielded, Metal Composite, 470 nH, 2.4 A, 0.064 ohm, SMD; Manufacturer: MuRata; Value: 470nH; Ind_H: 470.0E-9; Imax_A: 2.4; Irms: 2.4A @ 40C rise; Isat: 3.1A @ 30% inductance drop; DCR_ohm: 0.064; Value2: 2.4A; SizeAreaWB_mm2: 4.68; SizeArea_mm2: 1.28; SizeX_mm: 1.6; SizeY_mm: 0.8; AEC Category: Q200; AEC Qualified: N; Green_Lifecycle: Not Set; Green_REACh: Incomplete
R144-R146 R148-R150 R152-R154 R156-R158 = ERJ-2GE0R00X: as R54 on sheet AFE1-RX-INPUTS
R147 R151 R155 R159 = ERJ-2RKF1000X: RES, 100, 1%, 0.1 W, 0402; Manufacturer: Panasonic; CompType: Resistor; Value: 100; Value_Code: 100R; Tolerance_%: 1; Power_W: 0.1; Value2: 0.1W; VDC_V: 50; TempCo: 100 ppm/C; SizeArea_mm2: 0.5; SizeZ_mm: 0.6; EIA_Code: E96; U/M: EA; AEC Category: Q200; Green_Lifecycle: Active; Green_REACh: Passed
R545 = ERJ-2RKF49R9X: RES, 49.9, 1%, 0.1 W, AEC-Q200 Grade 0, 0402; Manufacturer: Panasonic; CompType: Resistor; Value: 49.9; Value_Code: 49R9; Tolerance_%: 1; Power_W: 0.1; Value2: 0.1W; VDC_V: 50; TempCo: 100 ppm/C; SizeArea_mm2: 0.5; SizeZ_mm: 0.6; EIA_Code: E96; U/M: EA; AEC Category: Q200; AEC Qualified: Y; AEC Grade: 0; Green_Lifecycle: Active; Green_REACh: Passed
T9-T12 = 1720BL15A0100: as T3 on sheet AFE1-RX-INPUTS
U81 = CMP-0079338-2: Multilayer Directional Coupler For 2400-2500MHz / 4900-5850MHz, SMD-4; Manufacturer: TDK; SizeZ_mm: 0.4; SizeArea_mm2: 0.5; SizeAreaWB_mm2: 3; SizeY_mm: 1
